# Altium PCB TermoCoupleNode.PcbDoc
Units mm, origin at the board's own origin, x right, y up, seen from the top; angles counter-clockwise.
Board outline 65 x 65 mm, 4 copper layers (Top Layer 1, GND, 3V3, Bottom Layer 1), stack 0.408 mm thick; 64 components, 46 nets, 247 pads, 276 vias.
Unrouted connection lines stored in the file: 64.
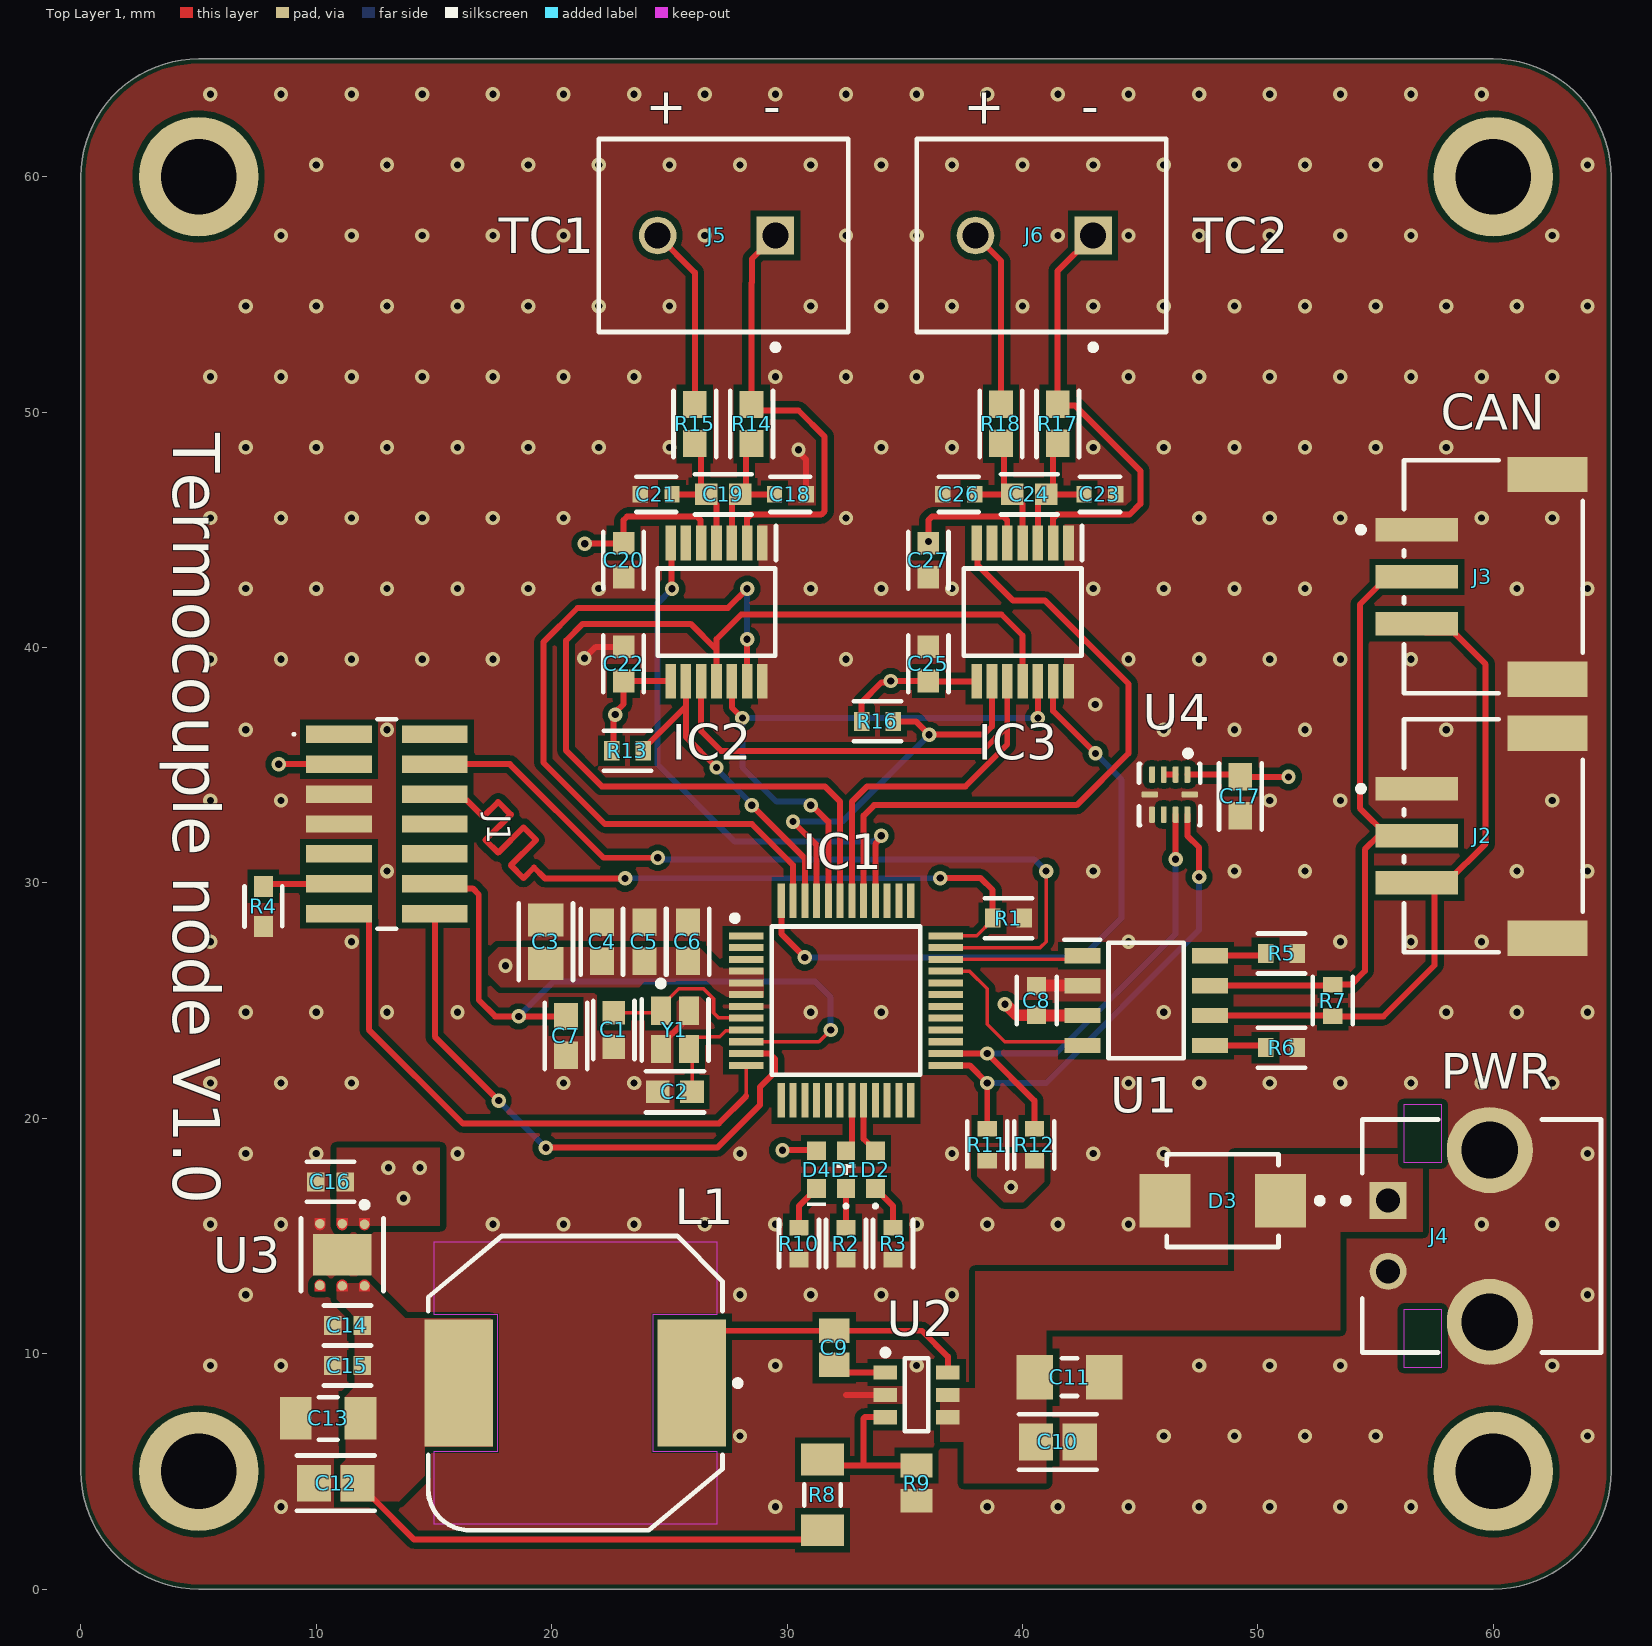
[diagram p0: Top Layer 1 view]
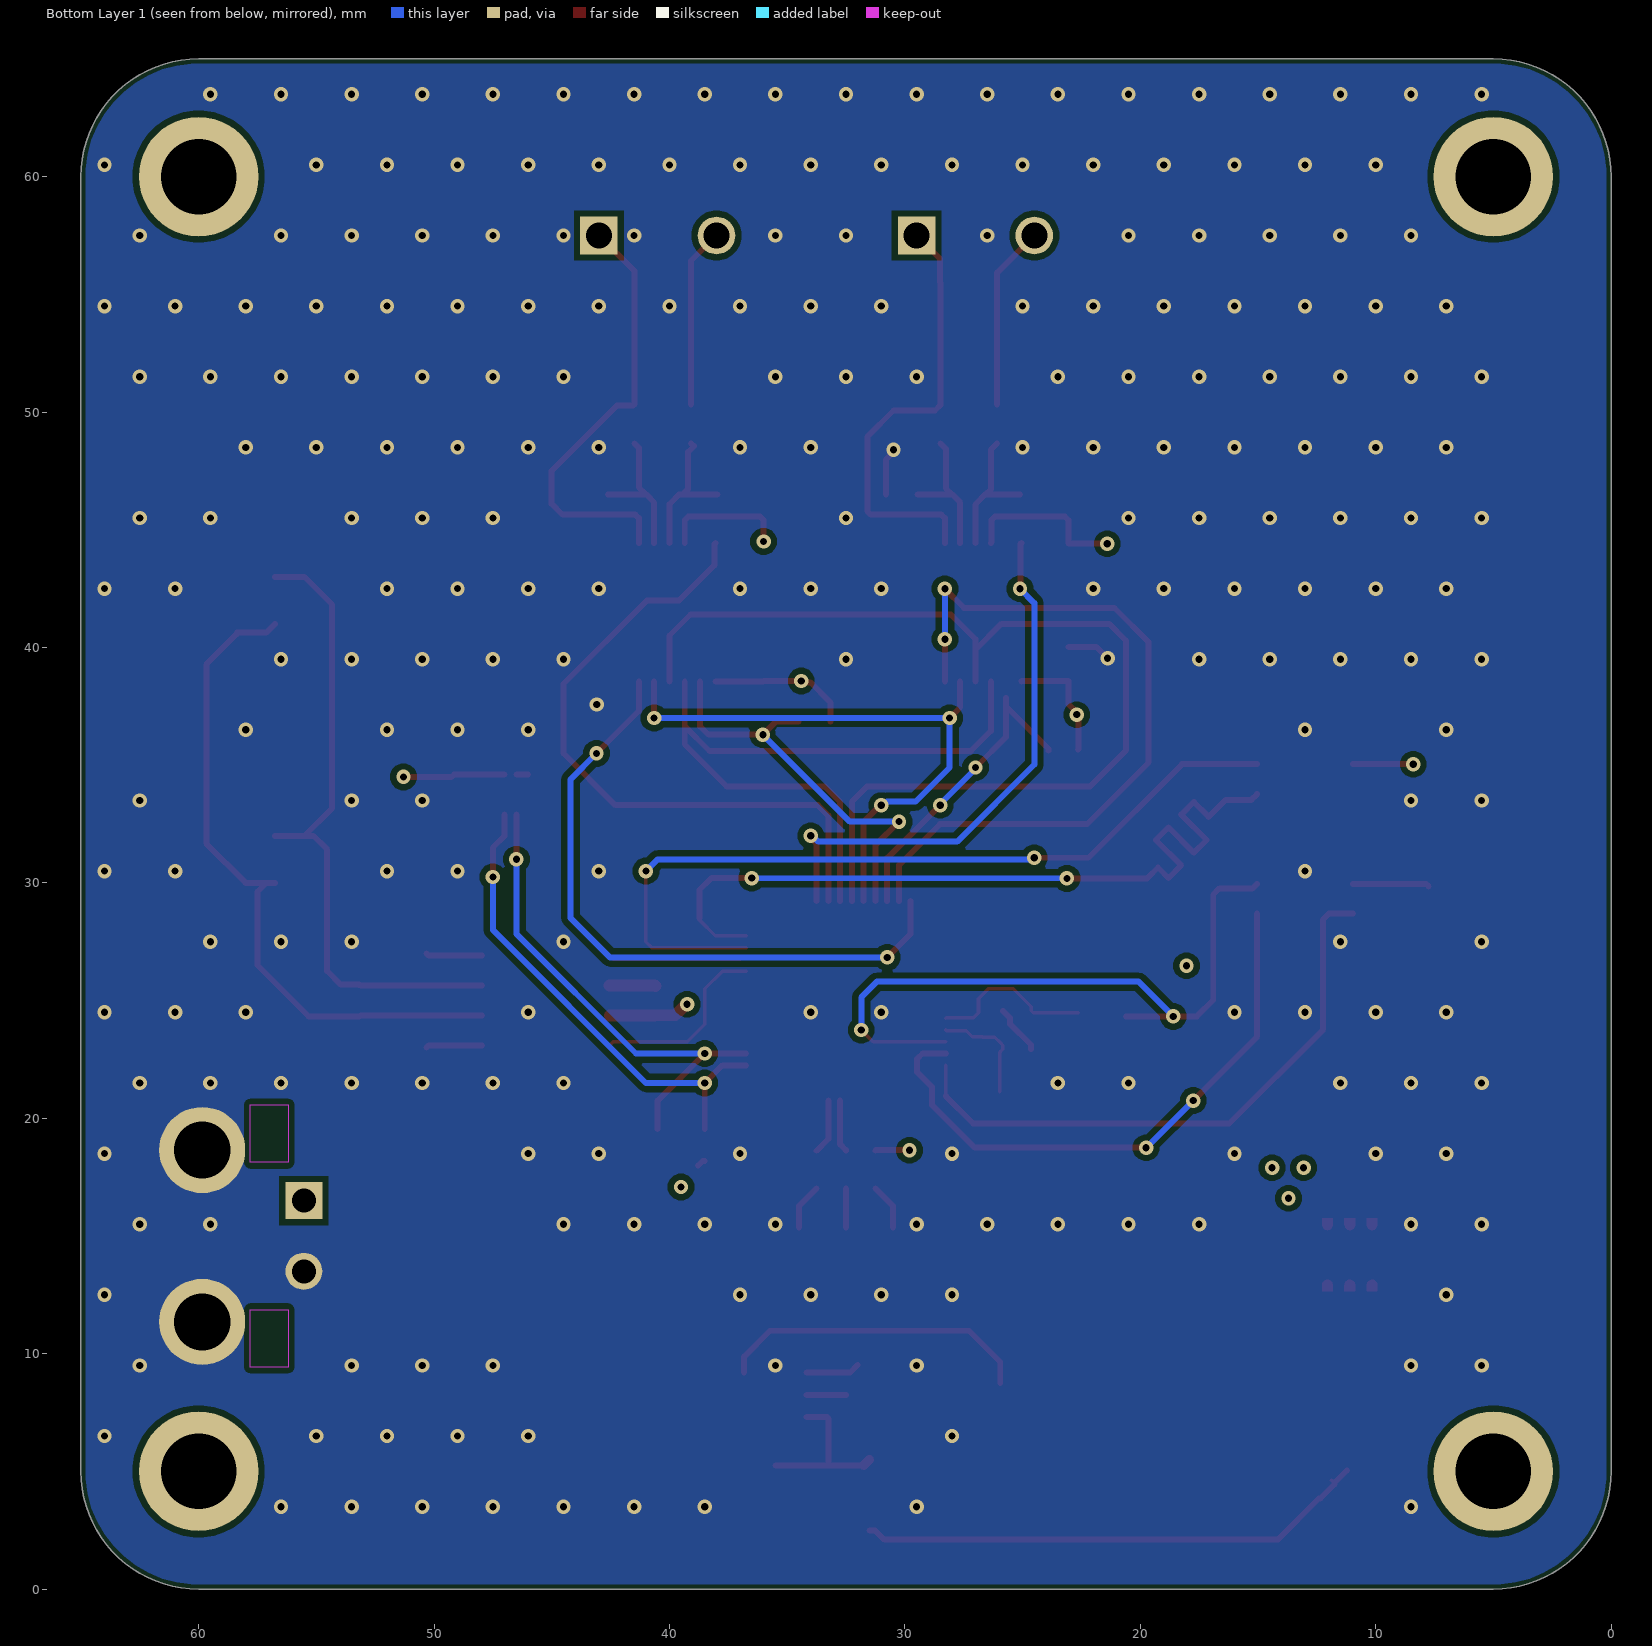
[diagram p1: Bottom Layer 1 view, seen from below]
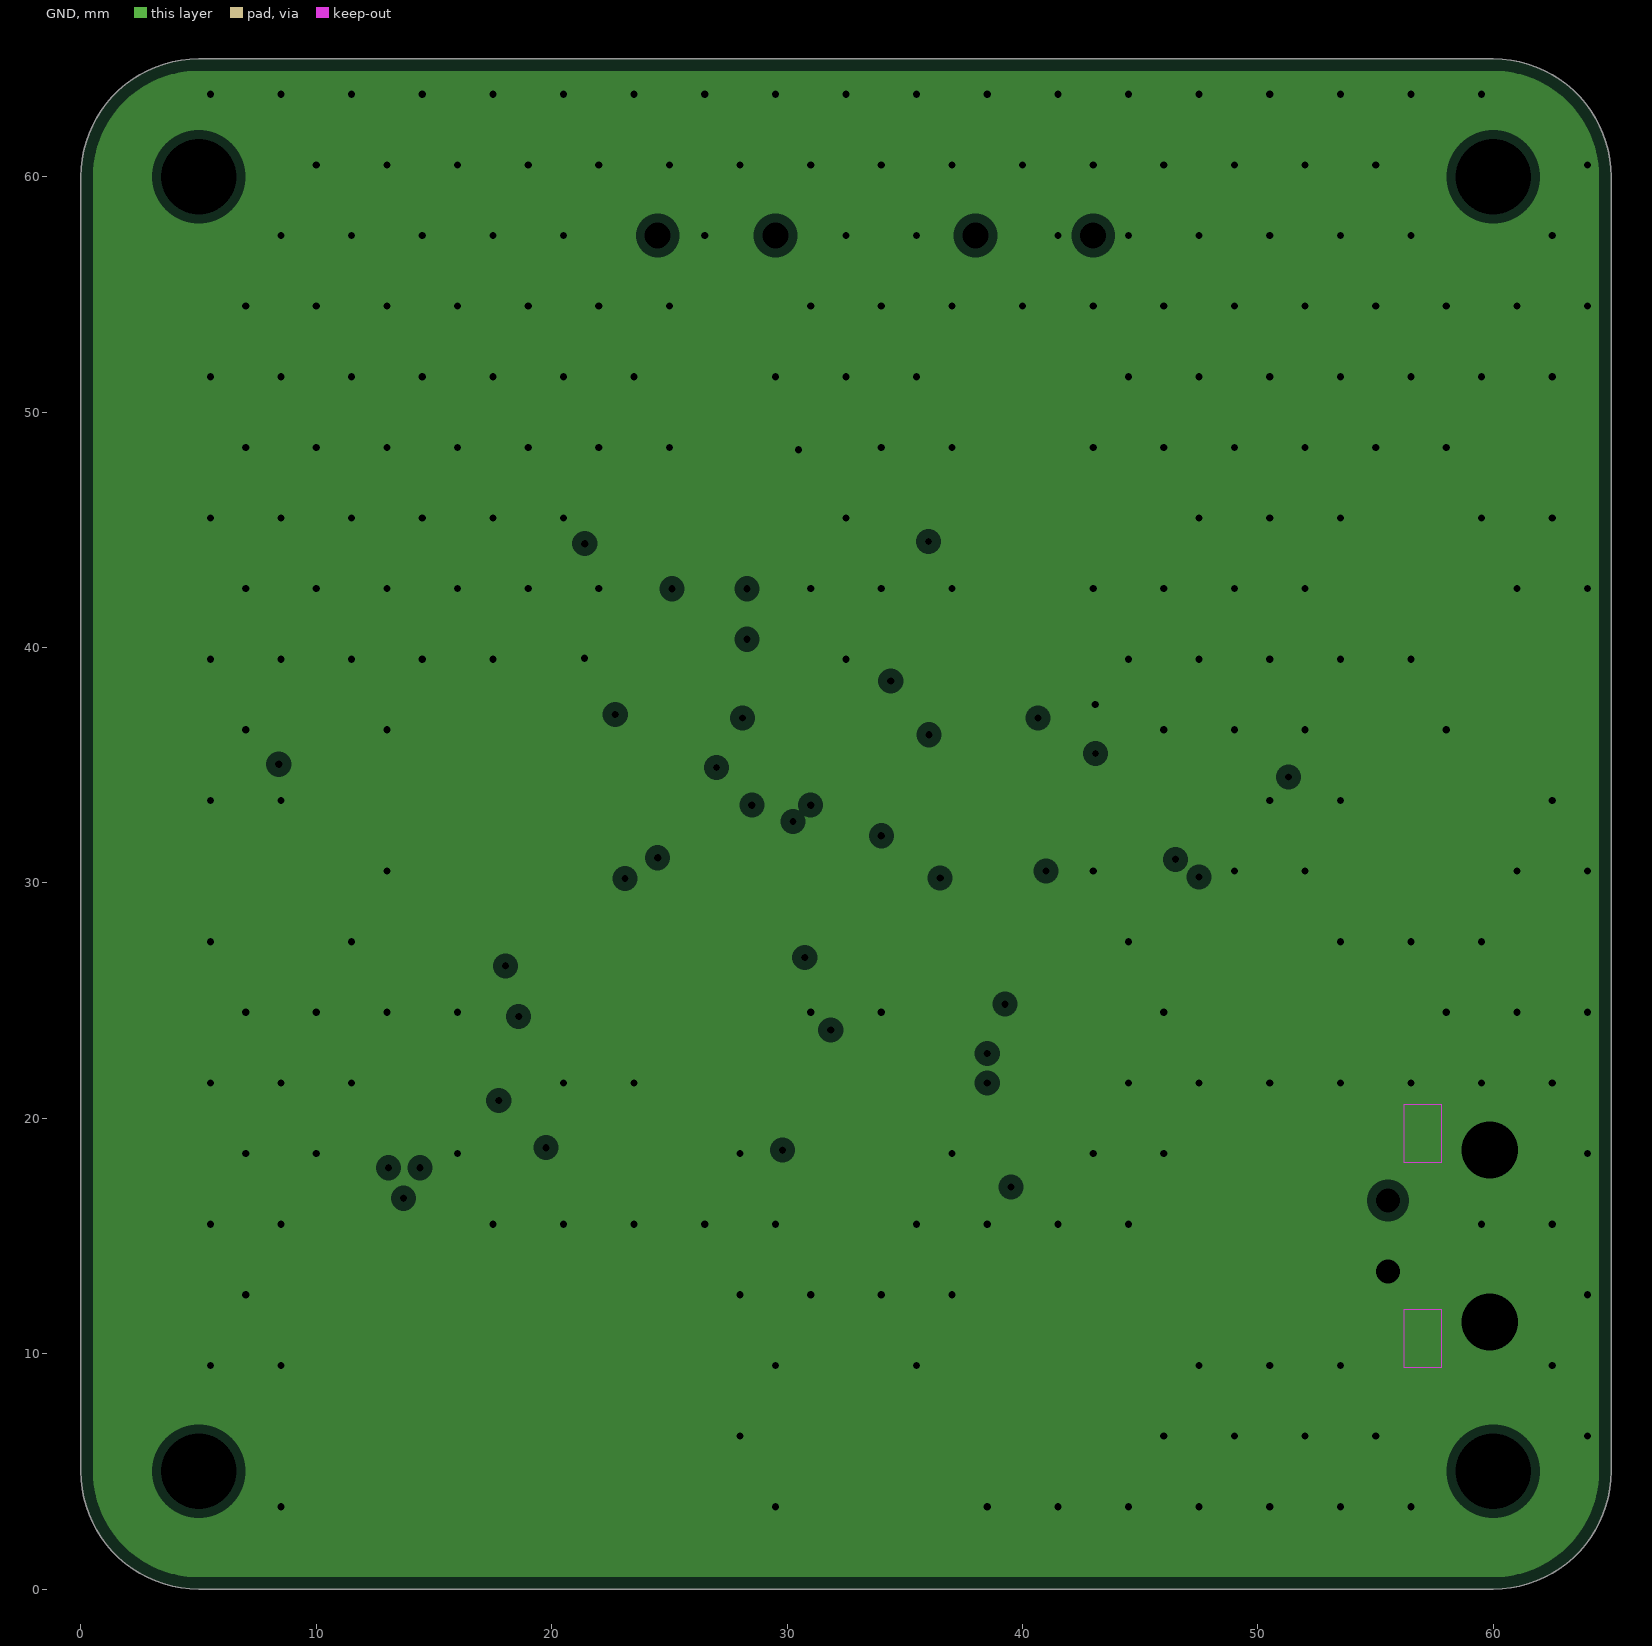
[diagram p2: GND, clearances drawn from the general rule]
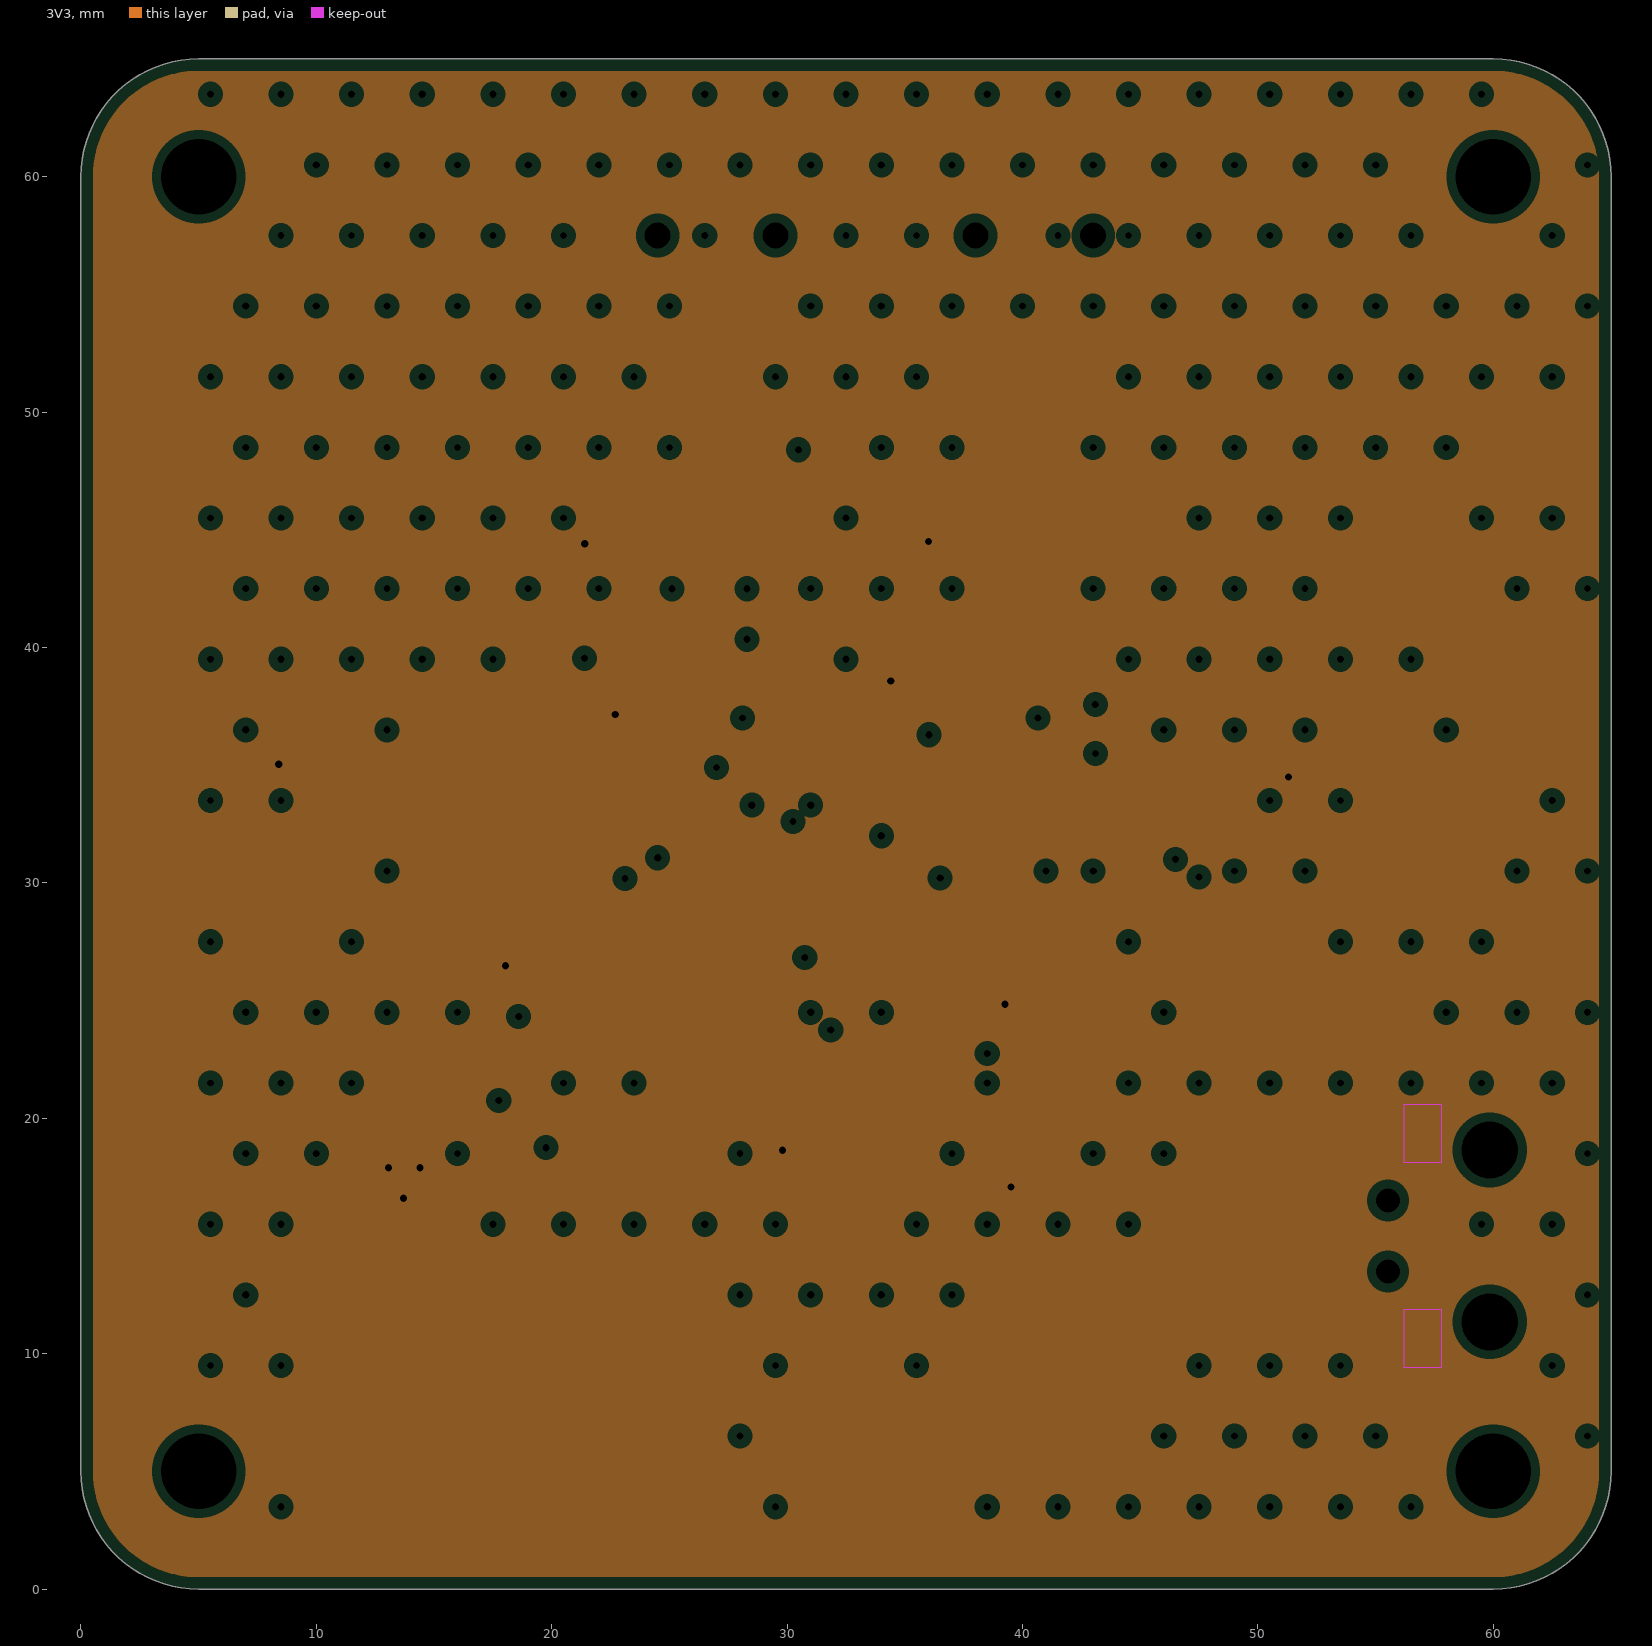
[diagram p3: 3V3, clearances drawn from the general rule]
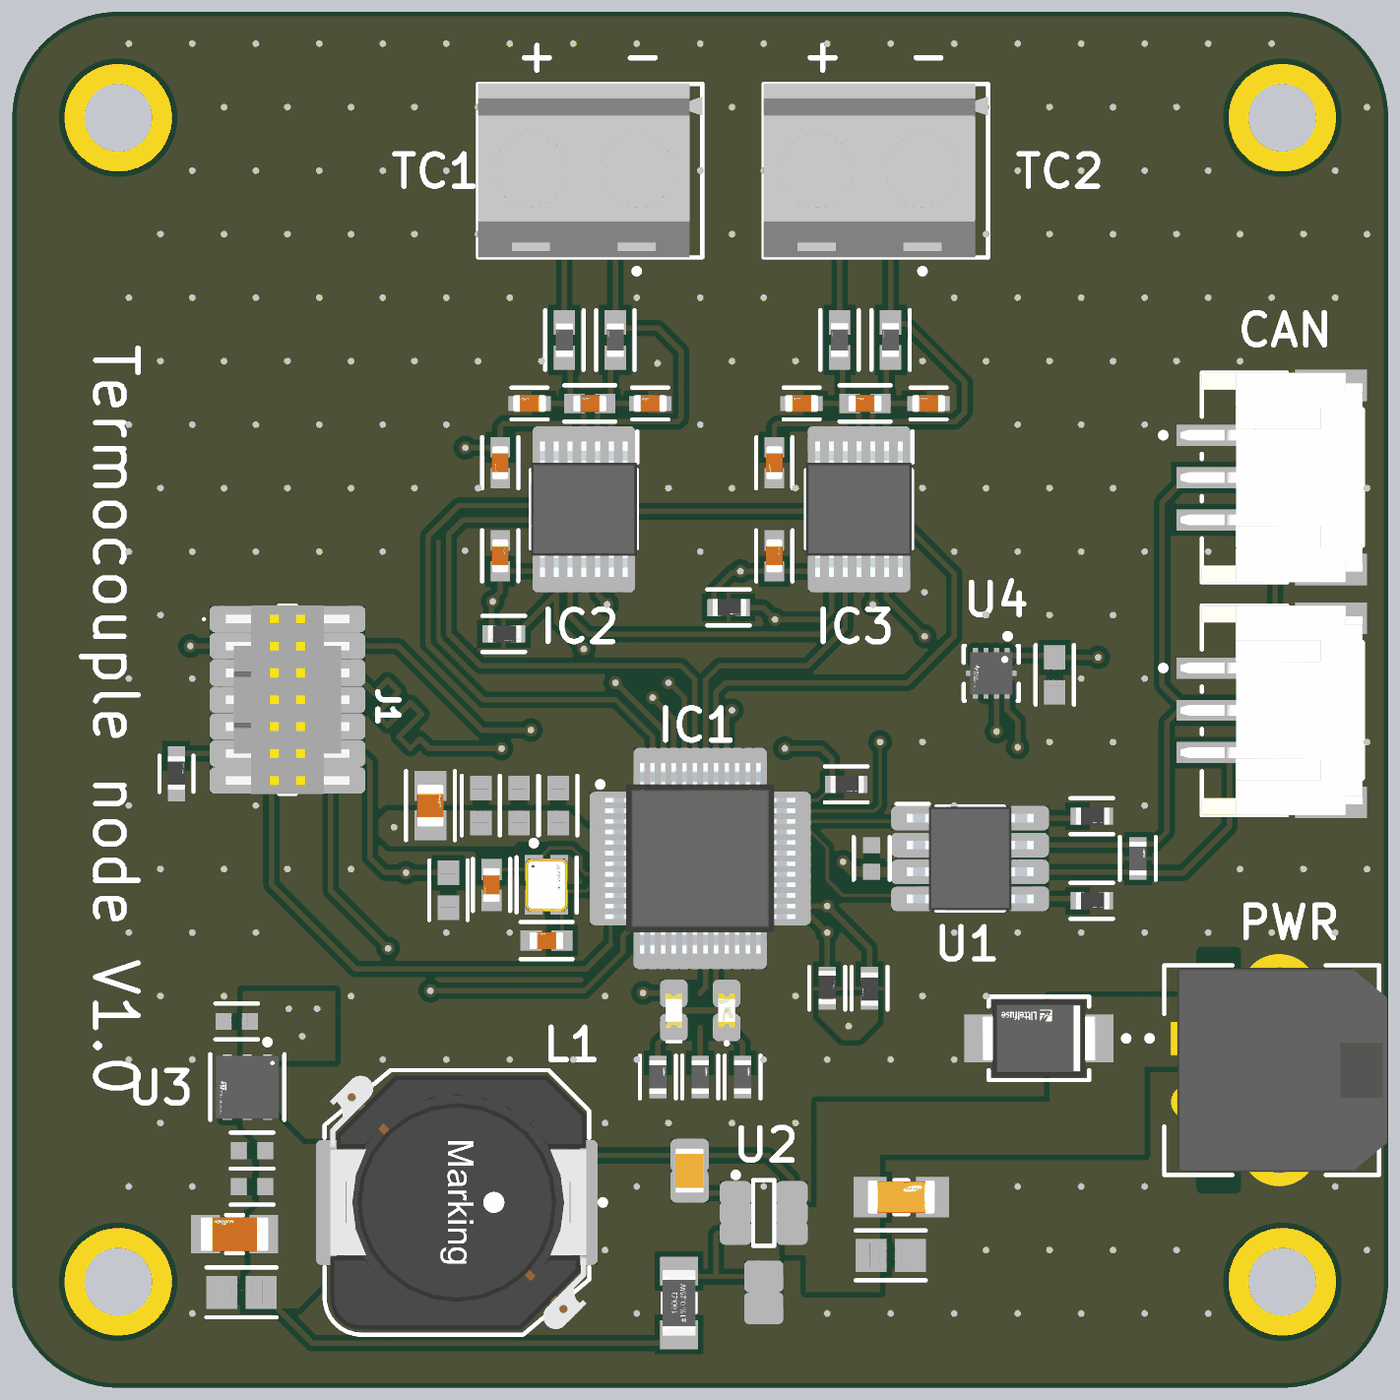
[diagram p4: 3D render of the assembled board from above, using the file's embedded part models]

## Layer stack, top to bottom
Top Solder: solder mask 0.0102, Solder Resist, Dk 3.5
Top Layer 1: signal copper 0.035
Dielectric 2: prepreg 0.0994, PP-006, Dk 4.1
GND: plane copper 0.0152, net GND
Dielectric 1: core 0.1088, FR-4, Dk 4.8
3V3: plane copper 0.0152, net 3V3
Dielectric 3: prepreg 0.0994, PP-006, Dk 4.1
Bottom Layer 1: signal copper 0.035
Bottom Solder: solder mask 0.0102, Solder Resist, Dk 3.5

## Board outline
0,5 ccw(c5,5) 5,0 60,0 ccw(c60,5) 65,5 65,60 ccw(c60,60) 60,65 5,65 ccw(c5,60) 0,60

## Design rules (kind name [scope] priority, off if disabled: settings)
BoardOutlineClearance [All] p1: gap=0.2 ignorepadtopadclearanceinfootprint=FALSE
Clearance "Stitching GND" [IsStitchingVia and InNet('GND') vs (IsVia and (Not IsStitchingVia)) Or IsPad] p1: gap=0.127 ignorepadtopadclearanceinfootprint=FALSE
Clearance [All] p2: gap=0.254 ignorepadtopadclearanceinfootprint=TRUE except(0.1: Arc-Arc Arc-Track Arc-SMDPad Track-Track Track-SMDPad; 0.15: Arc-Text Track-Text SMDPad-SMDPad SMDPad-Fill SMDPad-Poly SMDPad-Region SMDPad-Text THPad-Text Via-Text; 0.2: Arc-Via Track-Via; 0.35: Arc-THPad Track-THPad)
ComponentClearance ComponentClearance_1 [InComponent('L1','L2','L3','C24','C25','C26','C27') vs InComponent('L1','L2','L3','C24','C25','C26','C27')] p1 off: gap=0 collisioncheckmode=3 verticalgap=0 showdistances=FALSE
ComponentClearance [All] p2: gap=0 collisioncheckmode=3 verticalgap=0 showdistances=FALSE
DiffPairsRouting [All] p1: maxlimit=0.254 minlimit=0.254 mostfreqgap=0.254 toplayer_minwidth=0.254 toplayer_maxwidth=0.254 toplayer_prefwidth=0.254 bottomlayer_minwidth=0.254 bottomlayer_maxwidth=0.254 bottomlayer_prefwidth=0.254 maxuncoupledlength=12.7
HoleSize [All] p1: absolutevalues=TRUE maxlimit=7.62 minlimit=0.2 maxpercent=80.000 minpercent=20.000
MinimumAnnularRing [All] p1: minimumring=0.1
MinimumSolderMaskSliver [All] p1: minsoldermaskwidth=0.1
PasteMaskExpansion PasteMaskExpansion_1 [InPadClass('All Pads')] p1: expansion=0
PasteMaskExpansion [All] p2: expansion=0.254
PlaneClearance [All] p1: clearance=0.381
PlaneConnect [All] p1: pad.planeconnectstyle=Relief pad.reliefexpansion=0.508 pad.reliefentries=4 pad.reliefconductorwidth=0.254 pad.reliefairgap=0.254 via.planeconnectstyle=Direct via.reliefexpansion=0.508 via.reliefentries=4 via.reliefconductorwidth=0.254 via.reliefairgap=0.254
PolygonConnect [All] p1: connectstyle=Direct reliefconductorwidth=0.254 reliefentries=4 polygonreliefangle="90 Angle" airgapwidth=0.254
RoutingVias [All] p1: holewidth=0.305 width=0.61 viastyle="Through Hole" minholewidth=0.15 minwidth=0.25 maxholewidth=25.4 maxwidth=25.4
SMDNeckDown [All] p1 off: percent=100.000
SilkToSilkClearance [All] p1 off: silktosilkclearance=0.254
SilkToSolderMaskClearance SilkscreenOverComponentPads [IsPad] p1: minsilkscreentomaskgap=0.15 clearancetoexposedcopper=TRUE
SolderMaskExpansion [InPadClass('All Pads')] p1: expansion=0 istentingtop=FALSE useseparateexpansions=TRUE expansionbottom=0 istentingbottom=FALSE
SolderMaskExpansion SolderMaskExpansion_1 [All] p2: expansion=0.025 istentingtop=TRUE useseparateexpansions=TRUE expansionbottom=0.025 istentingbottom=TRUE
UnRoutedNet [All] p1: checkbadconnections=TRUE
Width [All] p1: maxlimit=1.27 minlimit=0.127 preferedwidth=0.254
20 further rules are at their usual default settings.

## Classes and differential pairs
component class "Local PCB temperature sensor": C17 R11 R12 U4
component class Designator: C18 C19 C20 C21 C22 C23 C24 C25 C26 C27 IC2 IC3 J5 J6 R R13 R14 R15 R16 R17 R18
component class Powersupply: C9 C10 C11 C12 C13 C14 C15 C16 D3 D4 J4 L1 R8 R9 R10 U2 U3
component class CAN_Tranceiver: C8 J2 J3 R5 R6 R7 U1
component class Toplevel: C1 C2 C3 C4 C5 C6 C7 D1 D2 IC1 J1 R1 R2 R3 R4 Y1

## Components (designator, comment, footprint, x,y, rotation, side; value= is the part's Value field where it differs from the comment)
C1 "4pF" FP-GQM187-0_15-IPC_B 22.637,23.75 r270 top
C2 "4pF" FP-GQM187-0_15-IPC_B 25.236,21.122 r180 top
C3 "4.7uF" FP-GCM21B-0_15-IPC_A 19.75,27.5 r90 top
C4 "100nF" FP-CL10-IPC_A 22.137,27.5 r90 top
C5 "100nF" FP-CL10-IPC_A 23.937,27.5 r90 top
C6 "100nF" FP-CL10-IPC_A 25.787,27.5 r90 top
C7 "100nF" FP-CL10-IPC_A 20.604,23.5 r270 top
C8 "1uF" FP-CL10-IPC_C 40.6,25 r90 top
C9 "Capacitor 100 nF +/-10% 50 V 0805" CAPC2013X95X50LL10T25 32,10.25 r270 top value=100nF
C10 "CL21B474KBFNNNF" FP-CL21-IPC_A 41.5,6.25 r0 top value=470nF
C11 "CL31B106KBHNNNE" FP-CL31B106KBHNNNE-IPC_A 42,9 r0 top value=10µF
C12 "CL21B474KBFNNNF" FP-CL21-IPC_A 10.824,4.5 r180 top value=470nF
C13 "GRM31CR61A476KE15K" FP-GRM31C-0_2-e0_3_0_8-IPC_B 10.5,7.25 r180 top value=47µF
C14 "100nF" FP-CL10-IPC_C 11.324,11.2 r180 top
C15 "10uF" FP-CL10-IPC_C 11.324,9.494 r180 top
C16 "10uF" FP-CL10-IPC_C 10.6,17.3 r180 top
C17 "100nF" FP-CL10-IPC_A 49.25,33.675 r270 top
C18 "10nF" FP-GCM188-0_1-MFG 30.135,46.5 r180 top
C19 "100nF" FP-GCM188-0_1-IPC_B 27.285,46.5 r180 top
C20 "100nF" FP-GCM188-0_1-IPC_B 23.05,43.7 r270 top
C21 "10nF" FP-GCM188-0_1-MFG 24.435,46.5 r180 top
C22 "100nF" FP-GCM188-0_1-IPC_B 23.05,39.3 r90 top
C23 "10nF" FP-GCM188-0_1-MFG 43.288,46.5 r180 top
C24 "100nF" FP-GCM188-0_1-IPC_B 40.288,46.5 r180 top
C25 "100nF" FP-GCM188-0_1-IPC_B 36,39.3 r90 top
C26 "10nF" FP-GCM188-0_1-MFG 37.288,46.5 r180 top
C27 "100nF" FP-GCM188-0_1-IPC_B 36,43.7 r270 top
D1 "150060GS55040" WL-SMCD_0603 -1237.5,1287.82 r90 top
D2 "150060YS75020" WL-SMCW_0603_150060xx75020 33.75,17.82 r90 top
D3 "SMBJ33A" FP-SMBJ-MFG 48.5,16.5 r180 top
D4 "150060RS75000" WL-SMCW_0603_150060xx75000 31.25,17.82 r90 top
IC1 "STM32G0B1CBT6" QFP50P900X900X160-48N 32.5,25 r0 top locked
IC2 "MAX31856MUD+" SOP65P640X110-14N 27,41.5 r270 top locked
IC3 "MAX31856MUD+" SOP65P640X110-14N 40,41.5 r270 top locked
J1 "FTSH-107-01-L-DV-K-TR" FTSH10701LDVKTR 13,32.5 r270 top
J2 "S3B-PH-SM4-TB(LF)(SN)" FP-S3B-PH-SM4-TB_LF_SN-MFG 60,32 r270 top locked
J3 "S3B-PH-SM4-TB(LF)(SN)" FP-S3B-PH-SM4-TB_LF_SN-MFG 60,43 r270 top locked
J4 "43650-0205" FP-43650-0205-MFG 59.5,15 r90 top locked
J5 "282836-2" TECO-282836-2_V 27,57.5 r180 top
J6 "282836-2" TECO-282836-2_V 40.5,57.5 r180 top
L1 "7447706330" WE-PD_1260P 21,8.75 r270 top value=33uH
R1 "10k" FP-RT0603-IPC_C 39.4,28.5 r0 top value=10KΩ
R2 "220 0603" FP-AF0603-IPC_C 32.5,14.677 r90 top
R3 "220 0603" FP-AF0603-IPC_C 34.5,14.677 r90 top
R4 "100" FP-RT0603-MFG 7.75,29 r90 top value=100Ω
R5 "10k" FP-RT0603-IPC_C 51,27 r0 top value=10KΩ
R6 "10k" FP-RT0603-IPC_C 51,23 r0 top value=10KΩ
R7 "120" FP-AF0603-IPC_C 53.175,25 r90 top
R8 "CRGCQ1206F100K" FP-CRGCQ1206-IPC_A 31.5,4 r90 top value=100k
R9 "ERA-6AEB1872V" RESC2013X60X40LL20T25 35.5,4.5 r270 top value=18.7k
R10 "220 0603" FP-AF0603-IPC_C 30.5,14.677 r90 top
R11 "10k" FP-RT0603-IPC_C 38.5,18.87 r90 top value=10KΩ
R12 "10k" FP-RT0603-IPC_C 40.5,18.87 r270 top value=10KΩ
R13 "10k" FP-RT0603-IPC_C 23.218,35.611 r0 top value=10KΩ
R14 "100" FP-CR0603-IPC_A 28.491,49.494 r90 top
R15 "100" FP-CR0603-IPC_A 26.079,49.494 r90 top
R16 "10k" FP-RT0603-IPC_C 33.838,36.86 r0 top value=10KΩ
R17 "100" FP-CR0603-IPC_A 41.494,49.5 r90 top
R18 "100" FP-CR0603-IPC_A 39.082,49.5 r90 top
U1 "TCAN3414DR" SOIC127P600X175-8N 45.25,25 r0 top locked
U2 "LMR51610XDBVR" SOT95P280X145-6N 35.5,8.25 r0 top
U3 "LD39200PU33R" FP-DFN6-7946637-MFG 11.1,14.2 r270 top
U4 "TMP461AIRUNR-S" FP-RUN0010A-MFG 46.25,33.75 r270 top
Y1 "ABM10W-50.0000MHZ-4-B1U-T3" FP-ABM10W-MFG 25.236,23.75 r270 top

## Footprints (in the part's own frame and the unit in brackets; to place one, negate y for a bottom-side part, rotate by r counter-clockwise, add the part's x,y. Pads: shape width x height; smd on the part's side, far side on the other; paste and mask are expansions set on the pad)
CAPC2013X95X50LL10T25 [mm] "Chip Capacitor, 2-Leads, Body 2.10x1.35mm, IPC High Density"
  rect 1.05x1.3 smd: 1(-0.725,0) 2(0.725,0)
  body extent -1.05,-0.67 1.05,0.67, height 0.95
FP-43650-0205-MFG [mm]
  rect 1.57x1.57 hole 1.02 paste-2539.97 mask+0: 1(1.5,3.97)
  round 1.57 hole 1.02 paste-2539.97 mask+0: 2(-1.5,3.97)
  round 3.66 hole 2.41 paste-2539.97 mask+0: 3(-3.65,-0.35) 4(3.65,-0.35)
  Keep-Out Layer region: 3.125,1.7 5.575,1.7 5.575,3.3 3.125,3.3
  Keep-Out Layer region: -5.575,1.7 -3.125,1.7 -3.125,3.3 -5.575,3.3
  silkscreen extent -4.95,-5.08 4.95,5.89, body extent -4.82,-5.45 4.83,4.45, height 6.07
FP-ABM10W-MFG [mm]
  rect 1.2x0.85 smd paste+0 mask+0: 1(-0.812,-0.6) 2(0.812,-0.6) 3(0.812,0.6) 4(-0.812,0.6)
  silkscreen extent -2.1,-1.42 1.3,1.42, body extent -1.51,-1.15 1.51,1.15, height 0.25
FP-AF0603-IPC_C [mm]
  rect 0.659x0.812 smd paste+0 mask+0: 1(-0.677,0) 2(0.677,0)
  silkscreen extent -1.01,-0.85 1.01,0.85, body extent -1.11,-0.55 1.11,0.55, height 0.25
FP-CL10-IPC_A [mm]
  rect 1.158x1.012 smd paste+0 mask+0: 1(-0.827,0) 2(0.827,0)
  silkscreen extent -1.41,-0.91 1.41,0.91, body extent -1.91,-1.01 1.91,1.01, height 0.25
FP-CL10-IPC_C [mm]
  rect 0.758x0.812 smd paste+0 mask+0: 1(-0.627,0) 2(0.627,0)
  silkscreen extent -1.01,-0.85 1.01,0.85, body extent -1.11,-0.55 1.11,0.55, height 0.25
FP-CL21-IPC_A [mm]
  rect 1.455x1.556 smd paste+0 mask+0: 1(-0.926,0) 2(0.926,0)
  silkscreen extent -1.65,-1.18 1.65,1.18, body extent -2.15,-1.28 2.15,1.28, height 0.25
FP-CL31B106KBHNNNE-IPC_A [mm]
  rect 1.554x1.906 smd paste+0 mask+0: 1(-1.476,0) 2(1.476,0)
  silkscreen extent -0.32,-0.8 0.32,0.8, body extent -2.75,-1.45 2.75,1.45, height 0.25
FP-CR0603-IPC_A [mm]
  rect 1.158x1.012 smd paste+0 mask+0: 1(-0.827,0) 2(0.827,0)
  silkscreen extent -1.41,-0.91 1.41,0.91, body extent -1.91,-1.01 1.91,1.01, height 0.25
FP-CRGCQ1206-IPC_A [mm]
  rect 1.356x1.81 smd paste+0 mask+0: 1(-1.501,0) 2(1.501,0)
  silkscreen extent -0.45,-0.77 0.45,0.78, body extent -2.68,-1.4 2.68,1.4, height 0.25
FP-DFN6-7946637-MFG [mm]
  round 0.405 smd paste+0 mask+0: 1(-1.3,0.95) 2(-1.321,0) 3(-1.321,-0.95) 4(1.3,-0.95) 5(1.321,0) 6(1.321,0.95)
  rect 1.75x2.5 smd paste+0 mask+0: 7(0,0)
  Top Layer 1 region: -1.55,-0.725 -1.275,-0.725 -1.189,-0.742 -1.116,-0.791 -1.067,-0.864 -1.05,-0.95 -1.05,-0.95 -1.067,-1.036 -1.116,-1.109 -1.189,-1.158 -1.275,-1.175 -1.275,-1.175 -1.55,-1.175
  Top Layer 1 region: -1.55,1.175 -1.275,1.175 -1.189,1.158 -1.116,1.109 -1.067,1.036 -1.05,0.95 -1.05,0.95 -1.067,0.864 -1.116,0.791 -1.189,0.742 -1.275,0.725 -1.275,0.725 -1.55,0.725
  Top Layer 1 region: -1.55,0.225 -1.275,0.225 -1.189,0.208 -1.116,0.159 -1.067,0.086 -1.05,0 -1.05,0 -1.067,-0.086 -1.116,-0.159 -1.189,-0.208 -1.275,-0.225 -1.275,-0.225 -1.55,-0.225
  Top Layer 1 region: 1.55,-1.175 1.275,-1.175 1.189,-1.158 1.116,-1.109 1.067,-1.036 1.05,-0.95 1.05,-0.95 1.067,-0.864 1.116,-0.791 1.189,-0.742 1.275,-0.725 1.275,-0.725 1.55,-0.725
  Top Layer 1 region: 1.55,-0.225 1.275,-0.225 1.189,-0.208 1.116,-0.159 1.067,-0.086 1.05,0 1.05,0 1.067,0.086 1.116,0.159 1.189,0.208 1.275,0.225 1.275,0.225 1.55,0.225
  Top Layer 1 region: 1.55,0.725 1.275,0.725 1.189,0.742 1.116,0.791 1.067,0.864 1.05,0.95 1.05,0.95 1.067,1.036 1.116,1.109 1.189,1.158 1.275,1.175 1.275,1.175 1.55,1.175
  silkscreen extent -2.25,-1.75 1.55,1.75, body extent -1.65,-1.65 1.65,1.65, height 0.25
FP-GCM21B-0_15-IPC_A [mm]
  rect 1.406x1.508 smd paste+0 mask+0: 1(-0.926,0) 2(0.926,0)
  silkscreen extent -1.63,-1.15 1.63,1.15, body extent -2.13,-1.25 2.13,1.25, height 0.25
FP-GCM188-0_1-IPC_B [mm]
  rect 0.959x0.912 smd paste+0 mask+0: 1(-0.727,0) 2(0.727,0)
  silkscreen extent -1.21,-0.86 1.21,0.86, body extent -1.46,-0.71 1.46,0.71, height 0.25
FP-GCM188-0_1-MFG [mm]
  rect 0.65x0.7 smd paste+0 mask+0: 1(-0.675,0) 2(0.675,0)
  silkscreen extent -0.85,-0.75 0.85,0.75, body extent -1.1,-0.55 1.1,0.55, height 0.25
FP-GQM187-0_15-IPC_B [mm]
  rect 1.007x0.958 smd paste+0 mask+0: 1(-0.726,0) 2(0.726,0)
  silkscreen extent -1.23,-0.88 1.23,0.88, body extent -1.48,-0.73 1.48,0.73, height 0.25
FP-GRM31C-0_2-e0_3_0_8-IPC_B [mm]
  rect 1.355x1.806 smd paste+0 mask+0: 1(-1.376,0) 2(1.376,0)
  silkscreen extent -0.4,-0.9 0.4,0.9, body extent -2.3,-1.15 2.3,1.15, height 0.25
FP-RT0603-IPC_C [mm]
  rect 0.659x0.812 smd paste+0 mask+0: 1(-0.677,0) 2(0.677,0)
  silkscreen extent -1.01,-0.85 1.01,0.85, body extent -1.11,-0.55 1.11,0.55, height 0.25
FP-RT0603-MFG [mm]
  rect 0.9x0.8 smd paste+0 mask+0: 1(-0.85,0) 2(0.85,0)
  silkscreen extent -0.85,-0.81 0.86,0.8, body extent -1.4,-0.55 1.4,0.55, height 0.25
FP-RUN0010A-MFG [mm]
  rrect40% 0.7x0.25 smd paste+0 mask+0: 1(-0.85,0.75) 2(-0.85,0.25) 3(-0.85,-0.25) 4(-0.85,-0.75) 6(0.85,-0.75) 7(0.85,-0.25) 8(0.85,0.25) 9(0.85,0.75)
  rrect40% 0.25x0.7 smd paste+0 mask+0: 5(0,-0.85) 10(0,0.85)
  silkscreen extent -1.87,-1.3 1.3,1.3, body extent -1.3,-1.3 1.3,1.3, height 0.25
FP-S3B-PH-SM4-TB_LF_SN-MFG [mm]
  rect 1x3.5 smd paste+0 mask+0: 1(-2,-3.25) 2(0,-3.25) 3(2,-3.25)
  rect 1.5x3.4 smd paste+0 mask+0: 4(-4.35,2.3) 5(4.35,2.3)
  silkscreen extent -4.95,-5.75 4.95,3.8, body extent -5.2,-5.1 5.2,4.1, height 0.25
FP-SMBJ-MFG [mm]
  rect 2.16x2.26 smd paste+0 mask+0: 1(-2.45,0) 2(2.45,0)
  silkscreen extent -4.25,-1.97 2.38,1.97, body extent -3.63,-2.07 3.63,2.07, height 0.25
FTSH10701LDVKTR [mm]
  rect 0.74x2.79 smd: 1(-3.81,-2.035) 2(-3.81,2.035) 3(-2.54,-2.035) 4(-2.54,2.035) 5(-1.27,-2.035) 6(-1.27,2.035) 7(0,-2.035) 8(0,2.035) 9(1.27,-2.035) 10(1.27,2.035) 11(2.54,-2.035) 12(2.54,2.035) 13(3.81,-2.035) 14(3.81,2.035)
  silkscreen extent -4.44,-4 4.45,0.4, body extent -4.45,-2.92 4.45,2.92, height 6.12
QFP50P900X900X160-48N [mm]
  rect 1.475x0.3 smd: 1(-4.238,2.75) 2(-4.238,2.25) 3(-4.238,1.75) 4(-4.238,1.25) 5(-4.238,0.75) 6(-4.238,0.25) 7(-4.238,-0.25) 8(-4.238,-0.75) 9(-4.238,-1.25) 10(-4.238,-1.75) 11(-4.238,-2.25) 12(-4.238,-2.75) 25(4.238,-2.75) 26(4.238,-2.25) 27(4.238,-1.75) 28(4.238,-1.25) 29(4.238,-0.75) 30(4.238,-0.25) 31(4.238,0.25) 32(4.238,0.75) 33(4.238,1.25) 34(4.238,1.75) 35(4.238,2.25) 36(4.238,2.75)
  rect 0.3x1.475 smd: 13(-2.75,-4.238) 14(-2.25,-4.238) 15(-1.75,-4.238) 16(-1.25,-4.238) 17(-0.75,-4.238) 18(-0.25,-4.238) 19(0.25,-4.238) 20(0.75,-4.238) 21(1.25,-4.238) 22(1.75,-4.238) 23(2.25,-4.238) 24(2.75,-4.238) 37(2.75,4.238) 38(2.25,4.238) 39(1.75,4.238) 40(1.25,4.238) 41(0.75,4.238) 42(0.25,4.238) 43(-0.25,4.238) 44(-0.75,4.238) 45(-1.25,4.238) 46(-1.75,4.238) 47(-2.25,4.238) 48(-2.75,4.238)
  silkscreen extent -4.85,-3.15 3.15,3.62, body extent -4.5,-4.5 4.5,4.5, height 1.6
RESC2013X60X40LL20T25 [mm] "Chip Resistor, 2-Leads, Body 2.00x1.25mm, IPC High Density"
  rect 1x1.35 smd: 1(-0.75,0) 2(0.75,0)
  body extent -1.1,-0.72 1.1,0.72, height 0.6
SOIC127P600X175-8N [mm]
  rect 1.525x0.65 smd: 1(-2.712,1.905) 2(-2.712,0.635) 3(-2.712,-0.635) 4(-2.712,-1.905) 5(2.712,-1.905) 6(2.712,-0.635) 7(2.712,0.635) 8(2.712,1.905)
  silkscreen extent -3.47,-2.45 1.6,2.58, body extent -3,-2.45 3,2.45, height 1.75
SOP65P640X110-14N [mm]
  rect 1.475x0.45 smd: 1(-2.938,1.95) 2(-2.938,1.3) 3(-2.938,0.65) 4(-2.938,0) 5(-2.938,-0.65) 6(-2.938,-1.3) 7(-2.938,-1.95) 8(2.938,-1.95) 9(2.938,-1.3) 10(2.938,-0.65) 11(2.938,0) 12(2.938,0.65) 13(2.938,1.3) 14(2.938,1.95)
  silkscreen extent -3.67,-2.5 1.85,2.52, body extent -3.2,-2.5 3.2,2.5, height 1.1
SOT95P280X145-6N [mm] "SOT23, 6-Leads, Body 2,90x2,80mm, Pitch 0,95mm, IPC Medium Density"
  rect 1x0.6 smd: 1(-1.325,0.95) 2(-1.325,0) 3(-1.325,-0.95) 4(1.325,-0.95) 5(1.325,0) 6(1.325,0.95)
  silkscreen extent -1.45,-1.55 0.5,1.92, body extent -0.88,-1.52 0.87,1.53, height 1.45
TECO-282836-2_V [mm] "Female Header, Pitch 5mm, 1 x 2 Position, Height 10mm"
  rect 1.6x1.6 hole 1.1: 1(-2.5,0)
  round 1.6 hole 1.1: 2(2.5,0)
  silkscreen extent -5.6,-4.1 5,4.87, body extent -5.6,-4.1 5,4.1, height 10
WE-PD_1260P [mm] "SMT Shielded Power Inductor, 2-leads, body 12x12mm"
  rect 5.4x2.9 smd: 1(0,4.95) 2(0,-4.95)
  Top Layer 1 keep-out region: -6,6 -2.9,6 -2.9,3.3 2.9,3.3 2.9,6 6,6 6,-6 2.9,-6 2.9,-3.3 -2.9,-3.3 -2.9,-6 -6,-6
  silkscreen extent -6.25,-6.25 6.25,7.03, body extent -5.99,-6.01 6.01,6.14, height 5.75
WL-SMCD_0603 [mm] "SMD Mono-color Chip LED, body 1.6x0.8mm"
  rect 0.8x0.75 smd: 1(-1270.8,-1270) 2(-1269.2,-1270)
  silkscreen extent -1271.62,-1270.4 -1269.78,-1269.6, body extent -1270.8,-1270.4 -1269.2,-1269.6, height 0.42
WL-SMCW_0603_150060xx75000 [mm] "SMD Mono-color Chip LED, body 1.60 x 0.80 mm"
  rect 0.8x0.8 smd: 1(-0.8,0) 2(0.8,0)
  silkscreen extent -1.55,-0.4 -1.4,0.4, body extent -0.8,-0.4 0.8,0.4, height 0.7
WL-SMCW_0603_150060xx75020 [mm] "SMD Mono-color Chip LED, body 1.6x0.8mm"
  rect 0.8x0.8 smd: 1(-0.8,0) 2(0.8,0)
  silkscreen extent -1.62,-0.08 -1.48,0.07, body extent -0.8,-0.4 0.8,0.4, height 0.25

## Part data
C1 C2: library part CMP-06035-061124-1, "GQM1875C2E4R0BB12D / Ceramic Capacitor 4pF ±0.1pF 250VDC C0G 0603 Paper T/R", Case Code (Imperial)=0603, Case Code (Metric)=1608, Dielectric=C0G, Max Operating Temperature=125°C, Min Operating Temperature=-55°C, Package Quantity=4000, Voltage Rating=250V
C3: library part CMP-2007-03343-2, "Ceramic Capacitor for Automotive 4.7uF ±10% 16VDC X7R 0805 Embossed T/R", Case Code (Imperial)=0805, Case Code (Metric)=2012, Dielectric=X7R, Max Operating Temperature=125°C, Min Operating Temperature=-55°C, Package Quantity=1, Ratings=AEC-Q200, Tolerance=10%, Voltage=16V
C4 C5 C6 C7 C17: library part CMP-13271-002683-1, "Cap Ceramic 100nF 16V X7R ±10% Pad SMD 0603 +125°C T/R", Case Code (Imperial)=0603, Case Code (Metric)=1608, Max Operating Temperature=125°C, Min Operating Temperature=-55°C, Ratings=AEC-Q200, Tolerance=10%, Voltage Rating=16V
C8: library part CMP-13271-000784-1, "Cap Ceramic 1uF 16V X7R ±10% Pad SMD 0603 +125°C T/R / CL10B105KO8NNNL", Case/Package=0603, Dielectric=X7R, Max Operating Temperature=125°C, Min Operating Temperature=-55°C, Package Quantity=15000, Tolerance=10%, Voltage Rating=16V
C9: library part CMP-001-00018-6, "Chip Capacitor, 100 nF, +/- 10%, 50 V, 0805 (2012 Metric)", Capacitor Type=Ceramic, Case/Package=0805, Max Operating Temperature=125°C, Min Operating Temperature=-55°C, Tolerance=10%, Voltage Rating=50V
C10 C12: library part CMP-001-00098-1, "Ceramic Capacitor, Multilayer, Ceramic, 50V, 10% +Tol, 10% -Tol, X7R, 15% TC, 0.47uF, Surface Mount, 0805", Capacitor Type=Ceramic, Case/Package=0805, Max Operating Temperature=125°C, Min Operating Temperature=-55°C, Package Shape=Rectangular, Package Style=SMTMeter, Rated DC Voltage (URdc)=50V, Temperature Characteristics Code=X7R, Tolerance  (fill in as +-)=10%
C11: library part CMP-001-00099-1, "Ceramic Capacitor, Multilayer, Ceramic, 50V, 10% +Tol, 10% -Tol, X7R, 15% TC, 10uF, Surface Mount, 1206", Capacitor Type=Ceramic, Case/Package=1206, Max Operating Temperature=125°C, Min Operating Temperature=-55°C, Package Shape=Rectangular, Package Style=SMTMeter, Rated DC Voltage (URdc)=50V, Temperature Characteristics Code=X7R, Tolerance  (fill in as +-)=10%
C13: library part CMP-001-00103-1, "Ceramic Capacitor, Multilayer, Ceramic, 10V, 10% +Tol, 10% -Tol, X5R, 15% TC, 47uF, Surface Mount, 1206", Capacitor Type=Ceramic, Case/Package=1206, Max Operating Temperature=85°C, Min Operating Temperature=-55°C, Package Shape=Rectangular, Package Style=SMTMeter, Rated DC Voltage (URdc)=10V, Temperature Characteristics Code=X5R, Tolerance  (fill in as +-)=10%
C14: library part CMP-13271-002683-1, "Cap Ceramic 100nF 16V X7R ±10% Pad SMD 0603 +125°C T/R / CL10B104KO8WPNC", Case Code (Imperial)=0603, Case Code (Metric)=1608, Max Operating Temperature=125°C, Min Operating Temperature=-55°C, Ratings=AEC-Q200, Tolerance=10%, Voltage Rating=16V
C15 C16: library part CMP-13271-003287-1, "Cap Ceramic 10uF 16V X6S ±20% Pad SMD 0603 +105°C T/R / CL10X106MO8NRNC", Case Code (Imperial)=0603, Case Code (Metric)=1608, Max Operating Temperature=105°C, Min Operating Temperature=-55°C, Tolerance=20%, Voltage Rating=16V
C18 C21 C23 C26: library part CMP-2006-02392-2, "Ceramic Capacitor for Automotive 10nF  ±10% 100VDC X7R 0603 Paper T/R", Case Code (Imperial)=0603, Case Code (Metric)=1608, Dielectric=X7R, Max Operating Temperature=125°C, Min Operating Temperature=-55°C, Package Quantity=1, Ratings=AEC-Q200, Tolerance=10%, Voltage=100V
C19 C20 C22 C24 C25 C27: library part CMP-2006-02353-3, "Ceramic Capacitor for Automotive 100nF  ±10% 50VDC X8L 0603 Paper T/R", Case Code (Imperial)=0603, Case Code (Metric)=1608, Dielectric=X8L, Max Operating Temperature=150°C, Min Operating Temperature=-55°C, Package Quantity=4000, Ratings=AEC-Q200, Tolerance=10%, Voltage=50V
D1: library part CMP-03913-90235563-2, "150060GS55040 WL-SMCD SMT Mono-color Chip LED Diffused", Forward Current=60mA, Forward Voltage=3.2V, Max Operating Temperature=85°C, Max Reverse Voltage (DC)=5V, Min Operating Temperature=-40°C
D2: library part CMP-03913-104891429-2, "WL-SMCW SMT Mono-Color Chip LED Waterclear super f", Forward Current=60mA, Forward Voltage=2V, Max Operating Temperature=85°C, Max Reverse Voltage (DC)=5V, Min Operating Temperature=-40°C
D3: library part CMP-2000-07095-2, "TVS DIODE 33V 53.3V DO214AA", Breakdown Voltage=36.7V, Clamping Voltage=53.3V, Manufacturer="Littelfuse Inc", Max Junction Temp=+150°C, Package=SMBJ, Peak Pulse Current=11.3A, Peak Pulse Power=600W, Reverse Standoff Voltage=33V, Temperature="-65°C to +150°C", Temperature Range Low=-65°C
D4: library part CMP-1426-00001-4, "LED Low-Power Uni-Color Red 630nm 2V 2-Pin Chip 0603(1608Metric) T/R", Case Code (Imperial)=0603, Case Code (Metric)=1608, Color=Red, Forward Current=100mA, Forward Voltage=2V, Max Junction Temperature (Tj)=95°C, Max Operating Temperature=85°C, Max Reverse Voltage (DC)=5V, Min Operating Temperature=-40°C, Power Dissipation=72mW, Test Current=20mA
IC1: "Integrated Circuit", Manufacturer_Name=STMicroelectronics, Mouser Part Number=511-STM32G0B1CBT6
IC2 IC3: "Integrated Circuit", Manufacturer_Name="Analog Devices", Mouser Part Number=700-MAX31856MUD+
J1: "Connector", Manufacturer_Name=SAMTEC, Mouser Part Number=200-FTSH10701LDVKTR
J2 J3: library part CMP-002-00113-1, "Connector Header, PH Series, 3 Position, Side Entry, 2.00mm, Solder, Surface Mount, Natural.", Max Current Rating=2A, Max Operating Temperature=85°C, Min Operating Temperature=-25°C, Voltage Rating=100V
J4: library part CMP-00257-07672643-1, "43650-0205 Conn Wire to Board HDR 2 POS 3mm Solder RA Side Entry Thru-Hole Micro-Fit 3.0™ Tray", Current Rating=5A, Manufacturer Lifecycle Status=ACTIVE, Voltage Rating=600V
J5 J6: library part CMP-1684-00017-1, "Female Header, Pitch 5 mm, 1 x 2 Position, Height 10 mm, Tail Length 3.5 mm, Rohs, Bulk", Color=Green, Current=13.5A, Manufacturer="TE Connectivity", Package Description="Female Header, Pitch 5 mm, 1 x 2 Position, Height 10 mm, Tail Length 3.5 mm", Package Reference=THD, Standard Package=300, Voltage=300V
L1: library part CMP-006-00028-1, "General Purpose Inductor"
R1 R5 R6 R11 R12 R13 R16: library part CMP-03412-005349-1, "RES SMD 10K OHM 1% 1/10W 0603 / RT0603FRE0710KL", Manufacturer=Yageo, Manufacturer Part Number=RT0603FRE0710KL, Package=RT0603, Power Rating=0.1W, Resistance=10KΩ, Temperature="-55°C to +155°C", Temperature Coefficient="50 ppm/°C", Temperature Range High=+155°C, Temperature Range Low=-55°C, Tolerance=0.01, Voltage Rating=75V
R2 R3 R10: library part CMP-03412-038529-1, "AF0603JR-07220RL Anti-Sulfurated Chip Resistors Automotive Grade 220Ω 5% 100ppm/°C 0603", Case/Package=0603, Max Operating Temperature=155°C, Max Power Dissipation=100mW, Min Operating Temperature=-55°C, Resistance=220R, Resistor Type="Thick Film", Temperature Coefficient=100ppm/°C, Tolerance=5%
R4: library part CMP-03412-030646-1, "RT0603 100Ω 0.1W 50 ppm/°C 1.00% RT0603FRE07100RL", Manufacturer=Yageo, Manufacturer Part Number=RT0603FRE10100RL, Package=RT0603, Power Rating=0.1W, Resistance=100Ω, Temperature="-55°C to +155°C", Temperature Coefficient="50 ppm/°C", Temperature Range High=+155°C, Temperature Range Low=-55°C, Tolerance=0.01, Voltage Rating=75V
R7: library part CMP-03412-039700-1, "Anti-Sulfurated Chip Resistors Automotive Grade 120Ω 1% 100ppm/°C 0603 AF0603FR-07120RL", Case/Package=0603, Max Operating Temperature=155°C, Max Power Dissipation=100mW, Min Operating Temperature=-55°C, Resistance=120R, Resistor Type="Thick Film", Temperature Coefficient=100ppm/°C, Tolerance=1%
R8: library part CMP-009-00192-1, "Fixed Resistor, Metal Glaze/thick Film, 0.25W, 100000ohm, 200V, 1% +/-Tol, 100ppm/Cel, Surface Mount, 1206", Resistor Type="FIXED RESISTOR"
R9: library part CMP-009-00195-1, "Fixed Resistor, Thin Film, 0.125W, 18700ohm, 100V, 0.1% +/-Tol, 25ppm/Cel, Surface Mount, 0805", Case/Package=0805, Max Operating Temperature=155°C, Min Operating Temperature=-55°C, Package Height=0.5mm, Package Length=2mm, Package Width=1.25mm, Power=125mW, Rated Temperature=85°C, Resistor Type="FIXED RESISTOR", Temperature Coefficient (ppm/Cel)=25, Tolerance=0.1%, Working Voltage=100V
R14 R15 R17 R18: library part CMP-07231-000376-1, "AEC-Q200 Compliant Chip Resistors 0603 100Ω 0.1W 1% 100ppm/°C"
U1: "Integrated Circuit", Manufacturer_Name="Texas Instruments", Mouser Part Number=595-TCAN3414DR
U2: library part CMP-019-00059-1, "SIMPLE SWITCHER® 4.5-V to 65-V, 1-A synchronous buck converter with 25-µA IQ 6-SOT-23 -40 to 150", Case/Package=SOT-23, Frequency=400Hz, Max Supply Voltage=65V, Min Supply Voltage=4.5V, Output Current=1A
U3: library part CMP-12153-000011-1, "IC REG LINEAR 3.3V 2A 6DFN", Case/Package=DFN, Dropout Voltage=130mV, Max Input Voltage=6V, Max Operating Temperature=125°C, Min Input Voltage=1.25V, Min Operating Temperature=-40°C, Operating Supply Current=1mA, Output Current=2A, Output Voltage=3.3V, Package Quantity=3000
U4: library part CMP-00370-103943066-1, "TMP461AIRUNR-S Temperature Sensor Digital, Local/Remote -40°C ~ 125°C 11 b 10-WQFN (2x2)", Manufacturer Lifecycle Status=ACTIVE
Y1: library part CMP-27762-007472-1, "Crystal 50MHz ±10ppm 4pF SMD-4 2.5mm x 2mm", Case/Package=SMD/SMT, ESR (Equivalent Series Resistance)=70R, Frequency=50MHz, Frequency Stability=10ppm, Load Capacitance=4pF, Max Operating Temperature=70°C, Min Operating Temperature=-20°C

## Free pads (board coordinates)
  round 5.08 hole 3.2: 2(5,5) 2(5,60) 2(60,5) 2(60,60)

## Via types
v1: diameter 0.61, hole 0.305, Top Layer 1 to Bottom Layer 1, tented both sides, 276 vias

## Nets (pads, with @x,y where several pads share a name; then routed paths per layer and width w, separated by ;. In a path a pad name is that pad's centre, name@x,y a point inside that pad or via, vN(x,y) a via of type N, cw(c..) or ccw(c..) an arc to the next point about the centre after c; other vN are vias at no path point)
3V3: C3.1 C4.1 C5.1 C6.1 C8.1 C16.1 C17.1 C20.1 C22.1 C25.1 C27.1 D4.2 IC1.4 IC1.5 IC1.6 IC2.5 IC2.8 IC3.5 IC3.8 J1.3 R11.1 R12.2 R13.1 R16.1 U1.3 U3.1 U3.2 U4.1 | length 35.8
  Top Layer 1 w0.254: v1(8.404,35.04) J1.3 ; v1(21.4,44.408) 23.031,44.408 C20.1 23.05,45.408 23.199,45.557 26.178,45.557 26.326,45.408 26.326,44.462 IC2.5 ; R13.1@22.65,35.671 22.632,35.689 22.632,37.077 v1(22.7,37.145) 22.7,37.241 23.05,37.591 C22.1 25.039,38.573 IC2.8 ; v1(29.802,18.645) 29.815,18.645 29.84,18.62 29.865,18.645 31.225,18.645 D4.2 ; R16.1 33.161,37.667 34.003,38.509 34.335,38.509 v1(34.4,38.573) C25.1 36.011,38.562 IC3.8 ; C27.1 v1(36,44.5) 36,45.406 36.15,45.557 39.201,45.557 39.35,45.408 IC3.5 ; R11.1 38.577,18.193 R11.1@38.779,17.991 ; U4.1 49.152,34.6 C17.1 v1(51.3,34.502)
  Top Layer 1 w0.5: v1(39.25,24.846) 39.286,24.846 39.753,24.379 40.594,24.379 C8.1 40.608,24.365 U1.3
  other v1: 13.7,16.6 39.511,17.081 13.062,17.9 14.4,17.9 18.037,26.475
5V0: C12.1 C13.1 C14.1 C15.1 L1.2 R8.1 U3.5 U3.6 | length 21.9
  Top Layer 1 w0.152: C12.1 C12.1@11.876,4.626
  Top Layer 1 w0.254: C12.1@11.225,5.035 11.755,4.505 11.755,4.444 12.35,3.849 12.411,3.849 14.16,2.1 30.874,2.1 31.273,2.499 R8.1
CANH: J2.2 J3.2 R7.2 U1.7 | length 28.9
  Top Layer 1 w0.254: U1.7 53.133,25.635 R7.2 53.962,25.677 54.54,26.255 54.54,31.421 55.119,32 J2.2 55.5,32 54.325,33.175 54.325,41.825 55.5,43 J3.2
CANL: J2.3 J3.3 R7.1 U1.6 | length 29.4
  Top Layer 1 w0.254: U1.6 53.133,24.365 R7.1 55.323,24.323 57.5,26.5 57.5,29.627 J2.3@57.127,30 ; J3.3 57.123,40.627 58.373,40.627 58.373,40.578 59.668,39.283 59.668,31.668 58,30 J2.3@57.127,30 ; J2.3@57.127,30 J2.3 J2.3@57.127,30
FB: R8.2 R9.1 U2.3 | length 7.1
  Top Layer 1 w0.25: R8.2@31.751,5.25 33.25,5.25 ; 33.25,7.251 33.25,5.25 ; R9.1 33.25,5.25
  Top Layer 1 w0.254: 33.25,7.251 33.299,7.3 U2.3
  Top Layer 1 w0.4: R8.2 R8.2@31.751,5.25
GND: C1.2 C2.2 C3.2 C4.2 C5.2 C6.2 C7.2 C8.2 C10.2 C11.2 C12.2 C13.2 C14.2 C15.2 C16.2 C17.2 C18.1 C20.2 C21.2 C22.2 C23.1 C25.2 C26.2 C27.2 D3.2 IC1.7 IC2.1 IC2.14 IC3.1 IC3.14 J1.5 J1.7 J2.1 J2.4 J2.5 J3.1 J3.4 J3.5 J4.2 J4.3 J4.4 R1.2 R2.1 R3.1 R4.1 R5.2 R6.2 R9.2 R10.1 U1.2 U2.2 U3.3 U3.7 U4.5 U4.6 U4.10 Y1.2 Y1.4 | length 9.6
  Top Layer 1 w0.254: v1(21.388,39.539) 21.876,40.027 C22.2 ; Y1.2 24.635,23.113 25.537,24.015 25.537,24.264 Y1.4 ; v1(30.484,48.396) 30.484,48.299 30.81,47.974 C18.1 ; 32.5,8.25 U2.2
  Top Layer 1 w0.508: C8.2 40.604,25.631 42.534,25.631 U1.2
  other v1: 8.5,3.5 29.5,3.5 38.5,3.5 41.5,3.5 44.5,3.5 47.5,3.5 50.5,3.5 53.5,3.5 56.5,3.5 28,6.5 46,6.5 49,6.5 52,6.5 55,6.5 64,6.5 5.5,9.5 8.5,9.5 29.5,9.5 35.5,9.5 47.5,9.5 50.5,9.5 53.5,9.5 62.5,9.5 7,12.5 28,12.5 31,12.5 34,12.5 37,12.5 64,12.5 5.5,15.5 8.5,15.5 17.5,15.5 20.5,15.5 23.5,15.5 26.5,15.5 29.5,15.5 35.5,15.5 38.5,15.5 41.5,15.5 44.5,15.5 59.5,15.5 62.5,15.5 7,18.5 10,18.5 16,18.5 28,18.5 37,18.5 43,18.5 46,18.5 64,18.5 5.5,21.5 8.5,21.5 11.5,21.5 20.5,21.5 23.5,21.5 44.5,21.5 47.5,21.5 50.5,21.5 53.5,21.5 56.5,21.5 59.5,21.5 62.5,21.5 7,24.5 10,24.5 13,24.5 16,24.5 31,24.5 34,24.5 46,24.5 58,24.5 61,24.5 64,24.5 5.5,27.5 11.5,27.5 44.5,27.5 53.5,27.5 56.5,27.5 59.5,27.5 13,30.5 43,30.5 49,30.5 52,30.5 61,30.5 64,30.5 5.5,33.5 8.5,33.5 50.5,33.5 53.5,33.5 62.5,33.5 7,36.5 13,36.5 46,36.5 49,36.5 52,36.5 58,36.5 43.091,37.575 5.5,39.5 8.5,39.5 11.5,39.5 14.5,39.5 17.5,39.5 32.5,39.5 44.5,39.5 47.5,39.5 50.5,39.5 53.5,39.5 56.5,39.5 7,42.5 10,42.5 13,42.5 16,42.5 19,42.5 22,42.5 31,42.5 34,42.5 37,42.5 43,42.5 46,42.5 49,42.5 52,42.5 61,42.5 64,42.5 5.5,45.5 8.5,45.5 11.5,45.5 14.5,45.5 17.5,45.5 20.5,45.5 32.5,45.5 47.5,45.5 50.5,45.5 53.5,45.5 59.5,45.5 62.5,45.5 7,48.5 10,48.5 13,48.5 16,48.5 19,48.5 22,48.5 25,48.5 34,48.5 37,48.5 43,48.5 46,48.5 49,48.5 52,48.5 55,48.5 58,48.5 5.5,51.5 8.5,51.5 11.5,51.5 14.5,51.5 17.5,51.5 20.5,51.5 23.5,51.5 29.5,51.5 32.5,51.5 35.5,51.5 44.5,51.5 47.5,51.5 50.5,51.5 53.5,51.5 56.5,51.5 59.5,51.5 62.5,51.5 7,54.5 10,54.5 13,54.5 16,54.5 19,54.5 22,54.5 25,54.5 31,54.5 34,54.5 37,54.5 40,54.5 43,54.5 46,54.5 49,54.5 52,54.5 55,54.5 58,54.5 61,54.5 64,54.5 8.5,57.5 11.5,57.5 14.5,57.5 17.5,57.5 20.5,57.5 26.5,57.5 32.5,57.5 35.5,57.5 41.5,57.5 44.5,57.5 47.5,57.5 50.5,57.5 53.5,57.5 56.5,57.5 62.5,57.5 10,60.5 13,60.5 16,60.5 19,60.5 22,60.5 25,60.5 28,60.5 31,60.5 34,60.5 37,60.5 40,60.5 43,60.5 46,60.5 49,60.5 52,60.5 55,60.5 64,60.5 5.5,63.5 8.5,63.5 11.5,63.5 14.5,63.5 17.5,63.5 20.5,63.5 23.5,63.5 26.5,63.5 29.5,63.5 32.5,63.5 35.5,63.5 38.5,63.5 41.5,63.5 44.5,63.5 47.5,63.5 50.5,63.5 53.5,63.5 56.5,63.5 59.5,63.5
LEDG: D1.2 IC1.19 | length 2.2
  Top Layer 1 w0.254: D1.2 32.5,18.645 32.75,18.895 IC1.19
LEDY: D2.2 IC1.20 | length 2.3
  Top Layer 1 w0.254: IC1.20 33.25,19.12 D2.2
NetC9_1: C9.1 L1.1 U2.6 | length 13.5
  Top Layer 1 w0.25: L1.1 25.95,9.65 27.275,10.975 C9.1 35.725,10.975 36.825,9.875 U2.6
NetC9_2: C9.2 U2.1 | length 2.3
  Top Layer 1 w0.25: C9.2 32.325,9.2 U2.1
NetD1_1: D1.1 R2.2 | length 1.7
  Top Layer 1 w0.254: R2.2 D1.1
NetD2_1: D2.1 R3.2 | length 2
  Top Layer 1 w0.254: D2.1 34.5,16.27 R3.2
NetD4_1: D4.1 R10.2 | length 2
  Top Layer 1 w0.254: R10.2 30.5,16.27 D4.1
NetIC1_33: IC1.33 U1.4 | length 8
  Top Layer 1 w0.152: IC1.33 37.75,26.25 38.5,25.5 38.5,24 39.25,23.25 42.383,23.25 U1.4
NetIC1_34: IC1.34 U1.1 | length 5.6
  Top Layer 1 w0.152: IC1.34@37,26.75 42.383,26.75 U1.1
NetJ1_11: J1.11 R4.2 | length 3.3
  Top Layer 1 w0.254: R4.2 7.86,29.96 J1.11
NetR5_1: R5.1 U1.8 | length 2.4
  Top Layer 1 w0.254: U1.8 50.228,26.905 R5.1
NetR6_1: R6.1 U1.5 | length 2.4
  Top Layer 1 w0.254: U1.5 50.228,23.095 R6.1
NetU4_2: U4.2 U4.3 | length 0.5
  Top Layer 1 w0.254: U4.3 U4.2
NRST: C7.1 IC1.10 J1.12 | length 29.8
  Top Layer 1 w0.152: IC1.10 31.35,23.25 v1(31.85,23.75)
  Top Layer 1 w0.254: J1.12 15.227,29.768 16.638,29.768 16.9,29.506 16.9,25.025 17.598,24.327 v1(18.596,24.327) C7.1
  Bottom Layer 1 w0.254: v1(18.596,24.327) 20.069,25.8 31.189,25.8 31.85,25.139 v1(31.85,23.75)
SCL: IC1.25 R11.2 U4.9 | length 20.8
  Top Layer 1 w0.254: IC1.25 37.75,22.25 v1(38.5,21.5) R11.2 ; U4.9 47,32 47.5,31.5 v1(47.5,30.25)
  Bottom Layer 1 w0.254: v1(38.5,21.5) 41,21.5 47.5,28 v1(47.5,30.25)
SDA: IC1.26 R12.1 U4.8 | length 21
  Top Layer 1 w0.254: IC1.26 v1(38.5,22.75) 40.5,20.75 R12.1 ; v1(46.5,31) U4.8
  Bottom Layer 1 w0.254: v1(38.5,22.75) 41.42,22.75 46.5,27.83 v1(46.5,31)
SPI1_MISO: IC1.43 IC2.11 IC3.11 | length 46.1
  Top Layer 1 w0.254: IC2.11 27,39.9 ; IC1.43 32.25,33.45 31.6,34.1 22.125,34.1 20.612,35.613 20.612,40.296 21.315,41 25.9,41 27,39.9 ; IC3.11 40,40.506 39.106,41.4 28.05,41.4 27,40.35 27,39.9
SPI1_MOSI: IC1.44 IC2.12 IC3.12 | length 25.9
  Top Layer 1 w0.254: IC2.12 27.65,37.45 v1(28.1,37) ; v1(31,33.3) 31.05,33.3 31.75,32.6 IC1.44 ; v1(40.65,37) IC3.12
  Bottom Layer 1 w0.254: v1(31,33.3) 30.904,33.3 30.754,33.45 29.55,33.45 28.1,34.9 v1(28.1,37) v1(40.65,37)
SPI1_SCK: IC1.42 IC2.10 IC3.10 | length 30.4
  Top Layer 1 w0.254: IC2.10 26.35,36.45 27.2,35.6 38.3,35.6 39.35,36.65 ; IC1.42 32.75,33.45 33.4,34.1 37.575,34.1 39.35,35.875 39.35,36.65 ; IC3.10 39.35,36.65
SpI_CS_T1: IC1.46 IC2.9 R13.2 | length 13.3
  Top Layer 1 w0.254: R13.2 23.895,35.688 25.7,37.493 ; IC2.9@25.7,37.844 25.7,37.493 ; v1(27,34.9) 25.7,36.2 25.7,37.493 ; v1(28.5,33.3) 30.75,31.05 IC1.46
  Bottom Layer 1 w0.254: v1(27,34.9) 27,34.85 28.5,33.35 v1(28.5,33.3)
SPI_CS_T2: IC1.45 IC3.9 R16.2 | length 17.6
  Top Layer 1 w0.254: v1(30.25,32.6) 31.25,31.6 IC1.45 ; R16.2 35.465,36.86 v1(36.032,36.292) 38.342,36.292 38.7,36.65 IC3.9
  Bottom Layer 1 w0.254: v1(30.25,32.6) 32.34,32.6 v1(36.032,36.292)
SWCLK: IC1.36 J1.6 R1.1 | length 35
  Top Layer 1 w0.152: IC1.36 38.05,27.75 38.723,28.423 R1.1
  Top Layer 1 w0.254: J1.6 15.278,33.527 16.373,33.527 17.003,32.897 17.093,32.807 17.723,33.437 18.262,32.898 17.182,31.818 17.721,31.279 18.801,32.359 19.34,31.82 18.26,30.74 18.798,30.201 19.249,30.652 19.662,30.238 19.709,30.191 v1(23.115,30.191) ; v1(36.5,30.2) 38.223,30.2 38.723,29.699 R1.1
  Bottom Layer 1 w0.254: v1(23.115,30.191) 23.12,30.196 36.496,30.196 v1(36.5,30.2)
SWDIO: IC1.35 J1.4 | length 35.2
  Top Layer 1 w0.152: IC1.35 40.75,27.25 41,27.5 v1(41,30.5)
  Top Layer 1 w0.254: J1.4 18.223,35.04 22.197,31.067 v1(24.5,31.067)
  Bottom Layer 1 w0.254: v1(24.5,31.067) 24.566,31 40.5,31 v1(41,30.5)
T1+: C19.2 C21.1 IC2.4 R15.1 | length 6.1
  Top Layer 1 w0.254: C21.1 C19.2 ; R15.1 26.35,48.396 26.35,46.708 C19.2 ; IC2.4 27,46.081 26.581,46.5 C19.2
T1-: C18.2 C19.1 IC2.3 R14.1 | length 6
  Top Layer 1 w0.254: IC2.3 27.65,46.162 27.988,46.5 C19.1 ; R14.1 28.262,48.438 28.262,46.75 C19.1 ; C18.2 C19.1
T1_DRDY: IC1.40 IC2.7 | length 23.5
  Top Layer 1 w0.254: IC2.7 25.08,44.408 25.08,42.524 v1(25.11,42.494) ; IC1.40 33.75,31.654 34,31.904 v1(34,32)
  Bottom Layer 1 w0.254: v1(25.11,42.494) 24.5,41.884 24.5,35.025 27.775,31.75 33.673,31.75 33.923,32 v1(34,32)
T1_FAULT: IC1.47 IC2.13 | length 32.6
  Top Layer 1 w0.254: IC2.13 v1(28.3,40.35) ; v1(28.3,42.494) 27.481,41.675 21.097,41.675 19.645,40.223 19.645,35.113 22.258,32.5 28.5,32.5 30.25,30.75 IC1.47
  Bottom Layer 1 w0.254: v1(28.3,40.35) v1(28.3,42.494)
T1_TERM_N: IC2.2 J5.1 R14.2 | length 18.9
  Top Layer 1 w0.254: IC2.2 28.3,45.495 28.449,45.644 31.445,45.644 31.594,45.793 31.594,48.955 30.484,50.065 28.72,50.065 28.491,50.294 28.491,55.491 28.5,55.5 28.5,56.5 J5.1
T1_TERM_P: J5.2 R15.2 | length 7.8
  Top Layer 1 w0.254: J5.2 26.079,55.921 R15.2
T2+: C24.2 C26.1 IC3.4 R18.1 | length 6.3
  Top Layer 1 w0.254: C26.1 C24.2@39.438,46.5 ; R18.1 38.957,48.548 39.211,48.294 39.211,48.079 39.218,48.072 39.218,46.721 C24.2@39.438,46.5 ; IC3.4 40,46.084 39.584,46.5 C24.2 C24.2@39.438,46.5
T2-: C23.2 C24.1 IC3.3 R17.1 | length 6.2
  Top Layer 1 w0.254: IC3.3 40.65,46.159 40.991,46.5 C24.1 ; R17.1 41.3,48.479 41.3,46.793 41.011,46.504 C24.1 ; C23.2 C24.1
T2_DRDY: IC1.41 IC3.7 | length 28.4
  Top Layer 1 w0.254: IC1.41 33.25,32.854 33.696,33.3 42.3,33.3 44.5,35.5 44.5,38.45 40.95,42 39.584,42 38.095,43.49 38.095,44.393 IC3.7
T2_FAULT: IC1.48 IC3.13 | length 28.2
  Top Layer 1 w0.254: IC1.48 29.75,27.835 v1(30.75,26.835) ; IC3.13 41.3,37.3 v1(43.1,35.5)
  Bottom Layer 1 w0.254: v1(30.75,26.835) 42.535,26.835 44.2,28.5 44.2,34.4 v1(43.1,35.5)
T2_TERM_N: IC3.2 J6.1 R17.2 | length 18.9
  Top Layer 1 w0.254: IC3.2 41.3,45.495 41.449,45.644 44.544,45.644 45,46.1 45,47.5 42.232,50.268 41.553,50.268 R17.2 41.494,55.994 J6.1
T2_TERM_P: J6.2 R18.2 | length 7.6
  Top Layer 1 w0.254: J6.2 39.082,56.418 R18.2
VCP_RX: IC1.12 J1.13 | length 25.5
  Top Layer 1 w0.152: 28.262,20.937 IC1.12
  Top Layer 1 w0.254: J1.13 11.99,28.69 12.233,28.447 12.233,23.767 16.225,19.775 27.1,19.775 28.262,20.937
VCP_TX: IC1.11 J1.14 | length 25.3
  Top Layer 1 w0.254: J1.14 15.035,23.465 v1(17.75,20.75) ; v1(19.75,18.75) 27.031,18.75 28.852,20.571 28.852,21.336 29.487,21.971 29.487,22.513 29.25,22.75 IC1.11
  Bottom Layer 1 w0.254: v1(17.75,20.75) v1(19.75,18.75)
Vin: C10.1 C11.1 D3.1 J4.1 U2.4 U2.5
XTAL2A: C1.1 IC1.8 Y1.1 | length 7
  Top Layer 1 w0.152: C1.1 24.549,24.476 Y1.1 24.635,24.737 25.398,25.5 26.449,25.5 26.872,25.077 26.872,24.476 27.083,24.265 28.247,24.265 IC1.8
XTAL2B: C2.1 IC1.9 Y1.3 | length 4.7
  Top Layer 1 w0.152: C2.1 25.961,22.812 Y1.3 25.835,23.098 25.919,23.182 26.184,23.447 26.686,23.447 26.699,23.459 27.138,23.459 27.392,23.714 28.226,23.714 28.245,23.733 IC1.9
pads on no net: IC1.1 IC1.2 IC1.3 IC1.13 IC1.14 IC1.15 IC1.16 IC1.17 IC1.18 IC1.21 IC1.22 IC1.23 IC1.24 IC1.27 IC1.28 IC1.29 IC1.30 IC1.31 IC1.32 IC1.37 IC1.38 IC1.39 IC2.6 IC3.6 J1.1 J1.2 J1.8 J1.9 J1.10 U3.4 U4.4 U4.7

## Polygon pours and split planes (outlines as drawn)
GND on Top Layer 1 "GND_L01_P010" (solid, pour order 10): 0,65 0,0 65,0 65,65
Vin on Top Layer 1 "VIN_L01_P009" (solid, pour order 9): 57,18.5 56.97,18.47 49,18.47 49,13.5 38,13.5 38,8.524 36.5,8.524 36.5,6.25 37.5,6.25 37.5,4.5 41,4.5 41,11 53.5,11 53.5,15.169 57,15.169
3V3 on Top Layer 1 "3V3_L01_P005" (solid, pour order 5): 27.53,25.098 27.544,25.113 29.007,25.113 29.007,26.374 28.982,26.4 27.138,26.4 26.268,27.27 17.72,27.27 17.3,26.85 17.3,26.1 17.825,25.575 23.712,25.575 23.937,25.8 26.465,25.8
5V0 on Top Layer 1 "5V0_L01_P007" (solid, pour order 7): 17.5,11.45 17.45,11.5 13.768,11.5 12.253,13.015 12.237,12.999 10.876,12.999 10.876,12.311 11.641,11.546 11.641,8.592 11.197,8.149 11.243,8.103 11.243,5.486 11.017,5.261 11.017,3.731 13.487,3.731 13.51,3.708 14.611,4.809 14.611,6.056 17.486,6.056
3V3 on Top Layer 1 "3V3_L01_P006" (solid, pour order 6): 38.086,18.514 38.086,17.534 39.195,16.425 40.025,16.425 40.914,17.314 40.914,18.521
3V3 on Top Layer 1 "3V3_L01_P001" (solid, pour order 1): 10.875,15.43 15.25,15.43 15.25,18.75 10.875,18.75
GND on Bottom Layer 1 "GND_L04_P011" (solid, pour order 11): 0,65 0,0 65,0 65,65
3V3 on 3V3 (split plane): 60.294,64.482 60.586,64.453 60.876,64.406 61.163,64.339 61.444,64.253 61.719,64.15 61.987,64.029 62.246,63.89 62.496,63.735 62.734,63.564 62.962,63.377 63.176,63.176 63.377,62.962 63.564,62.734 63.735,62.496 63.89,62.246 64.029,61.987 64.15,61.719 64.253,61.444 64.339,61.163 64.406,60.876 64.453,60.586 64.482,60.294 64.491,60.018 64.49,60 64.49,5 64.491,4.982 64.482,4.706 64.453,4.414 64.406,4.124 64.339,3.837 64.253,3.556 64.15,3.281 64.029,3.013 63.89,2.754 63.735,2.504 63.564,2.266 63.377,2.038 63.176,1.824 62.962,1.623 62.734,1.436 62.496,1.265 62.246,1.11 61.987,0.971 61.719,0.85 61.444,0.747 61.163,0.661 60.876,0.594 60.586,0.547 60.294,0.518 60.018,0.509 60,0.51 5,0.51 4.982,0.509 4.706,0.518 4.414,0.547 4.124,0.594 3.837,0.661 3.556,0.747 3.281,0.85 3.013,0.971 2.754,1.11 2.504,1.265 2.266,1.436 2.038,1.623 1.824,1.824 1.623,2.038 1.436,2.266 1.265,2.504 1.11,2.754 0.971,3.013 0.85,3.281 0.747,3.556 0.661,3.837 0.594,4.124 0.547,4.414 0.518,4.706 0.509,4.982 0.51,5 0.51,60 0.509,60.018 0.518,60.294 0.547,60.586 0.594,60.876 0.661,61.163 0.747,61.444 0.85,61.719 0.971,61.987 1.11,62.246 1.265,62.496 1.436,62.734 1.623,62.962 1.824,63.176 2.038,63.377 2.266,63.564 2.504,63.735 2.754,63.89 3.013,64.029 3.281,64.15 3.556,64.253 3.837,64.339 4.124,64.406 4.414,64.453 4.706,64.482 4.982,64.491 5,64.49 60,64.49 60.018,64.491
GND on GND (split plane): 60.294,64.482 60.586,64.453 60.876,64.406 61.163,64.339 61.444,64.253 61.719,64.15 61.987,64.029 62.246,63.89 62.496,63.735 62.734,63.564 62.962,63.377 63.176,63.176 63.377,62.962 63.564,62.734 63.735,62.496 63.89,62.246 64.029,61.987 64.15,61.719 64.253,61.444 64.339,61.163 64.406,60.876 64.453,60.586 64.482,60.294 64.491,60.018 64.49,60 64.49,5 64.491,4.982 64.482,4.706 64.453,4.414 64.406,4.124 64.339,3.837 64.253,3.556 64.15,3.281 64.029,3.013 63.89,2.754 63.735,2.504 63.564,2.266 63.377,2.038 63.176,1.824 62.962,1.623 62.734,1.436 62.496,1.265 62.246,1.11 61.987,0.971 61.719,0.85 61.444,0.747 61.163,0.661 60.876,0.594 60.586,0.547 60.294,0.518 60.018,0.509 60,0.51 5,0.51 4.982,0.509 4.706,0.518 4.414,0.547 4.124,0.594 3.837,0.661 3.556,0.747 3.281,0.85 3.013,0.971 2.754,1.11 2.504,1.265 2.266,1.436 2.038,1.623 1.824,1.824 1.623,2.038 1.436,2.266 1.265,2.504 1.11,2.754 0.971,3.013 0.85,3.281 0.747,3.556 0.661,3.837 0.594,4.124 0.547,4.414 0.518,4.706 0.509,4.982 0.51,5 0.51,60 0.509,60.018 0.518,60.294 0.547,60.586 0.594,60.876 0.661,61.163 0.747,61.444 0.85,61.719 0.971,61.987 1.11,62.246 1.265,62.496 1.436,62.734 1.623,62.962 1.824,63.176 2.038,63.377 2.266,63.564 2.504,63.735 2.754,63.89 3.013,64.029 3.281,64.15 3.556,64.253 3.837,64.339 4.124,64.406 4.414,64.453 4.706,64.482 4.982,64.491 5,64.49 60,64.49 60.018,64.491

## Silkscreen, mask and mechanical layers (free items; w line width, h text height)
Top Overlay:
  text "+" at 23.992,62.238 h1.52
  text "-" at 28.992,62.238 h1.52
  text "+" at 37.492,62.238 h1.52
  text "-" at 42.492,62.238 h1.52
  text "TC1" at 17.754,56.754 h1.52
  text "TC2" at 47.254,56.754 h1.52
  text "CAN" at 57.754,49.254 h1.52
  text "Termocouple node V1.0" at 3.921,49.104 h2 r270
  text "PWR" at 57.754,21.254 h1.52
Bottom 3D Body:
  lines w0.254: 0,0 65,0 65,65 0,65 0,0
